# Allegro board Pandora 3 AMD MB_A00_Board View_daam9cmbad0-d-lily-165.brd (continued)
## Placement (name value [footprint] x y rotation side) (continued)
R785  1K/F_4  [R0402]  141.82 133.63 270 bottom
R786  1K/F_4  [R0402]  169.86 105.3 0 top
R787  1K/F_4  [R0402]  170.23 98.85 0 top
R788  2.37K/F_4  [R0402]  133.13 139.96 270 top
R789  2.37K/F_4  [R0402]  151.98 128.17 90 top
R790  2.37K/F_4  [R0402]  176.73 112.31 270 top
R791  2.37K/F_4  [R0402]  162.23 90.08 270 top
R792  5.49K/F_4  [R0402]  131.09 139.96 270 top
R793  5.49K/F_4  [R0402]  152.36 126.65 180 top
R794  5.49K/F_4  [R0402]  177.75 112.31 270 top
R795  5.49K/F_4  [R0402]  163.24 90.08 270 top
R796  2.37K/F_4  [R0402]  129.44 124.72 180 top
R797  2.37K/F_4  [R0402]  149.06 139.86 270 top
R798  2.37K/F_4  [R0402]  164.47 117.36 90 top
R799  2.37K/F_4  [R0402]  177.69 92.73 180 top
R800  5.49K/F_4  [R0402]  129.44 125.74 180 top
R801  5.49K/F_4  [R0402]  151.09 139.86 270 top
R802  5.49K/F_4  [R0402]  164.02 115.97 180 top
R803  5.49K/F_4  [R0402]  178.6 90.45 0 top
R804  2.37K/F_4  [R0402]  123.38 133.13 0 top
R805  2.37K/F_4  [R0402]  156.88 138.18 90 top
R806  2.37K/F_4  [R0402]  173.41 121.14 90 bottom
R807  2.37K/F_4  [R0402]  169.61 83.16 270 bottom
R808  5.49K/F_4  [R0402]  122.87 134.98 90 top
R809  5.49K/F_4  [R0402]  157.27 135.56 180 top
R810  5.49K/F_4  [R0402]  171.12 121.14 90 bottom
R811  5.49K/F_4  [R0402]  170.75 83.16 270 bottom
R812  *s0402_NC  [S0402]  74.56 123.92 270 bottom
R813  *s0402_NC  [S0402]  75.58 123.92 270 bottom
R816  *s0402_NC  [S0402]  71.04 120.93 270 bottom
R817  *s0402_NC  [S0402]  72.05 120.93 270 bottom
R821  6.2K/F_4  [R0402]  248.48 13.44 0 bottom
R831  *s0402_NC  [S0402]  269.58 54.88 0 top
R832  *s0402_NC  [S0402]  269.58 56.02 0 top
R833  *10K/F_4_NC  [R0402]  264.86 50.91 0 top
R834  *10K/F_4_NC  [R0402]  262.95 50.91 0 top
R835  *10K/F_4_NC  [R0402]  266.76 57 90 top
R836  *10K/F_4_NC  [R0402]  265.62 57 270 top
R852  *s0603_NC  [S0603]  217.41 11 180 top
R861  100K_4  [R0402]  220.26 19.54 270 bottom
R862  100K_4  [R0402]  221.86 17.76 270 bottom
R863  4.7K_4  [R0402]  230.95 28.81 90 top
R864  4.7K_4  [R0402]  229.81 28.81 90 top
R865  2.2K_4  [R0402]  226.76 28.81 90 top
R866  2.2K_4  [R0402]  225.06 28.81 90 top
R867  2.2K_4  [R0402]  238.95 23.55 0 top
R868  2.2K_4  [R0402]  238.95 25.2 0 top
R872  100K/F_4  [R0402]  212.91 20.6 180 top
R876  10K/F_4  [R0402]  249.24 36.68 270 bottom
R878  10K/F_4  [R0402]  238.76 24.43 0 bottom
R886  *s0402_NC  [S0402]  193.13 21.34 90 bottom
R899  *0_4_NC  [R0402]  179.69 49.73 0 top
R908  *s0603_NC  [S0603]  246.14 17.66 270 bottom
R909  *s0402_NC  [S0402]  248.48 15.73 0 bottom
R910  *s0402_NC  [S0402]  248.48 14.58 0 bottom
R913  *4.7K_4_NC  [R0402]  104.71 53.19 90 top
R914  *4.7K_4_NC  [R0402]  105.86 53.19 90 top
R915  *s0402_NC  [S0402]  105.25 51.34 90 top
R916  *s0402_NC  [S0402]  106.39 51.34 90 top
R917  4.7K_4  [R0402]  104.71 59.54 90 top
R918  *4.7K_4_NC  [R0402]  106.11 59.54 90 top
R919  *0_4_NC  [R0402]  104.71 57.38 90 top
R920  *s0402_NC  [S0402]  105.82 57.38 90 top
R921  150/F_4  [R0402]  147.13 86.85 90 bottom
R922  *1K/F_4_NC  [R0402]  124.14 103.87 180 bottom
R923  *1K/F_4_NC  [R0402]  122.11 103.87 0 bottom
R924  *1K/F_4_NC  [R0402]  119.97 107.3 180 top
R925  1K/F_4  [R0402]  117.82 106.1 0 top
R926  1K/F_4  [R0402]  140.57 95.94 0 top
R927  *1K/F_4_NC  [R0402]  140.57 94.92 180 top
R928  *1K/F_4_NC  [R0402]  124.14 105.01 180 bottom
R929  1K/F_4  [R0402]  122.11 105.01 0 bottom
R930  1K/F_4  [R0402]  117.79 105.01 0 bottom
R931  *1K/F_4_NC  [R0402]  119.95 105.01 180 bottom
R932  1K/F_4  [R0402]  117.79 103.87 0 bottom
R933  *1K/F_4_NC  [R0402]  119.95 103.87 180 bottom
R934  1K/F_4  [R0402]  119.95 102.72 180 bottom
R935  *1K/F_4_NC  [R0402]  117.79 102.72 0 bottom
R936  *1K/F_4_NC  [R0402]  139.13 93.94 90 top
R937  1K/F_4  [R0402]  138.11 93.94 270 top
R938  1K/F_4  [R0402]  119.95 111.87 0 top
R939  *1K/F_4_NC  [R0402]  119.95 110.72 180 top
R940  *1K/F_4_NC  [R0402]  117.79 114.53 0 top
R941  *1K/F_4_NC  [R0402]  117.79 115.55 180 top
R942  *1K/F_4_NC  [R0402]  117.79 109.45 0 top
R943  *1K/F_4_NC  [R0402]  117.79 110.47 180 top
R944  10/F_4  [R0402]  122.11 110.72 0 bottom
R945  *10/F_4_NC  [R0402]  124.14 110.72 180 bottom
R946  *10/F_4_NC  [R0402]  124.14 109.58 180 bottom
R947  10/F_4  [R0402]  122.11 109.58 0 bottom
R948  *10/F_4_NC  [R0402]  117.79 109.58 0 bottom
R949  10/F_4  [R0402]  119.95 109.58 180 bottom
R950  10/F_4  [R0402]  124.14 108.44 180 bottom
R951  *10/F_4_NC  [R0402]  122.11 108.44 0 bottom
R952  10/F_4  [R0402]  117.79 108.44 0 bottom
R953  *10/F_4_NC  [R0402]  119.95 108.44 180 bottom
R954  10/F_4  [R0402]  117.79 107.48 0 bottom
R955  *10/F_4_NC  [R0402]  119.95 107.29 180 bottom
R956  *10/F_4_NC  [R0402]  124.14 107.29 180 bottom
R957  10/F_4  [R0402]  122.11 107.29 0 bottom
R958  10/F_4  [R0402]  117.79 106.15 0 bottom
R959  *10/F_4_NC  [R0402]  119.95 105.97 180 bottom
R960  *10K/F_NC  [R0402]  122.37 85.7 270 bottom
R962  *s0603_NC  [S0603]  274.97 83.59 180 top
R963  *100K/F_4_NC  [R0402]  221.81 28.81 90 top
R964  *s0402_NC  [S0402]  220.66 28.81 270 top
R965  *10K/F_4_NC  [R0402]  95.95 101.1 180 bottom
R966  10K_4  [R0402]  239 20.43 180 top
R967  10K_4  [R0402]  217.77 25.68 0 top
R970  24.3K/F_4  [R0402]  241.24 13.35 180 top
R971  20K/F_4  [R0402]  239.01 13.35 0 top
R981  *10K/F_4_NC  [R0402]  21.73 18.88 0 bottom
R982  *10K/F_4_NC  [R0402]  20.32 24.49 90 bottom
R983  *10K/F_4_NC  [R0402]  21.31 24.49 270 bottom
R984  *10K/F_4_NC  [R0402]  19.98 18.88 0 bottom
R985  *10K/F_4_NC  [R0402]  21.37 12.35 270 bottom
R986  *10K/F_4_NC  [R0402]  21.73 17.89 0 bottom
R987  *10K/F_4_NC  [R0402]  19.98 17.89 0 bottom
R988  *10K/F_4_NC  [R0402]  20.36 12.35 90 bottom
R994  10K/F_4  [R0402]  88.99 106.05 270 top
R1002  *100K_4_NC  [R0402]  247.03 20.96 0 top
R1003  *15K/F_4_NC  [R0402]  269.43 83.16 90 top
R1004  *0_4_NC  [R0402]  269.3 77.58 180 top
R1005  10K/F_4  [R0402]  228.77 28.81 270 top
R1006  *10K/F_4_NC  [R0402]  97.63 104.3 270 bottom
R1007  10K/F_4  [R0402]  117.01 85.78 0 bottom
R1008  *10K/F_4_NC  [R0402]  95.95 112.09 180 bottom
R1009  *10K/F_4_NC  [R0402]  95.95 111.07 180 bottom
R1010  10K/F_4  [R0402]  78.68 115.93 90 top
R1011  10K/F_4  [R0402]  89.26 103.25 0 top
R1012  10K/F_4  [R0402]  98.16 101.66 90 bottom
R1013  10K/F_4  [R0402]  117.79 116.57 180 top
R1014  *10K/F_4_NC  [R0402]  136.36 83.98 0 top
R1015  *0_4_NC  [R0402]  123.25 83.35 0 bottom
R1016  4.7K_4  [R0402]  123.25 84.32 180 bottom
R1017  *s0402_NC  [S0402]  270.79 50.75 0 top
R1018  *s0402_NC  [S0402]  270.79 51.73 0 top
R1020  *s0402_NC  [S0402]  154.18 51.4 270 bottom
R1021  *10K/F_4_NC  [R0402]  161.28 36.45 0 bottom
R1022  *s0402_NC  [S0402]  160.62 40.41 0 bottom
R1023  *s0402_NC  [S0402]  158.69 36.17 0 bottom
R1024  *s0402_NC  [S0402]  153.97 40.37 0 bottom
R1026  *0_4_NC  [R0402]  155.83 40.36 0 bottom
R1027  10K/F_4  [R0402]  158.77 40.46 0 bottom
R1028  *s0402_NC  [S0402]  157.35 37.57 270 bottom
R1029  *0_4_NC  [R0402]  157.35 39.38 90 bottom
R1030  10K/F_4  [R0402]  153.1 35.79 180 bottom
R1031  *s0402_NC  [S0402]  155.83 41.38 0 bottom
R1032  *0_4_NC  [R0402]  152.1 40.35 0 bottom
R1034  *s0402_NC  [S0402]  148.21 40.26 0 bottom
R1035  *0_4_NC  [R0402]  148.21 39.3 180 bottom
R1036  *s0402_NC  [S0402]  258.1 16.95 270 bottom
R1037  *0_4_NC  [R0402]  182.85 53.82 90 bottom
R1038  *s0402_NC  [S0402]  176.72 42.65 90 top
R1040  10K_4  [R0402]  228.54 30.26 0 top
R1042  *s0402_NC  [S0402]  127.55 52.63 270 bottom
R1043  *s0402_NC  [S0402]  122.11 30.08 270 bottom
R1044  *s0402_NC  [S0402]  212.36 15.31 0 top
R1045  10K_4  [R0402]  242.76 21.32 90 top
R1046  *s0402_NC  [S0402]  243.78 21.32 270 top
R1048  *s0402_NC  [S0402]  223.99 29.11 0 bottom
R1049  *0_4_NC  [R0402]  223.99 28.1 0 bottom
R1050  *s0402_NC  [S0402]  168.86 55.96 180 bottom
R1051  *s0402_NC  [S0402]  171.39 54.08 90 bottom
R1052  *s0402_NC  [S0402]  26.1 13.95 0 top
R1053  *s0402_NC  [S0402]  26.1 12.93 180 top
R1054  *1M_4_NC  [R0402]  17.08 9.5 90 bottom
R1055  *0_4_NC  [R0402]  138.01 28.81 90 bottom
R1056  *22_8_NC  [R0805]  99.3 124.57 90 bottom
R1057  *22_8_NC  [R0805]  77.41 127.35 180 bottom
R1058  *22_8_NC  [R0805]  57.57 126.72 90 bottom
R1059  *22_8_NC  [R0805]  115.93 19.41 0 bottom
R1060  *22_8_NC  [R0805]  18.23 7.22 0 bottom
R1061  *22_8_NC  [R0805]  133.13 25.15 180 bottom
R1062  *22_8_NC  [R0805]  31.18 69.58 90 bottom
R1063  *1M_4_NC  [R0402]  125.82 44.1 90 top
R1064  *0_4_NC  [R0402]  128.46 46.53 180 bottom
R1065  *22_8_NC  [R0805]  123.99 43.28 90 bottom
R1066  *s0402_NC  [S0402]  46.32 115.82 180 bottom
R1067  *100K_4_NC  [R0402]  122.81 89.37 0 bottom
R1068  *s0402_NC  [S0402]  181.42 13.17 0 bottom
R1069  *0_4_NC  [R0402]  12.09 23.03 0 bottom
R1070  8.2K_4  [R0402]  220.16 22.54 90 bottom
R1071  *s0402_NC  [S0402]  217.77 24.24 180 top
R1072  *100K_4_NC  [R0402]  217.87 16.49 0 bottom
R1073  *0_4_NC  [R0402]  153.17 51.4 90 bottom
R1074  100K_4  [R0402]  232.74 31.67 270 top
R1075  *s0402_NC  [S0402]  243.78 23.09 270 top
R1076  *s0402_NC  [S0402]  242.76 23.09 270 top
R1077  *22_8_NC  [R0805]  137.28 79.62 0 bottom
R1078  *1M_4_NC  [R0402]  124.13 80.62 270 bottom
R1079  *0_4_NC  [R0402]  124.4 78.92 0 bottom
R1080  *s0603_NC  [S0603]  263.97 49.72 180 top
R1082  1K/F_4  [R0402]  75.31 120.93 90 bottom
R1083  33_4  [R0402]  140.32 86.76 0 bottom
R1084  33_4  [R0402]  134.48 86.76 0 bottom
R1085  33_4  [R0402]  136.25 86.76 0 bottom
R1086  33_4  [R0402]  138.54 86.76 0 bottom
R1087  *s0402_NC  [S0402]  26.1 7.73 0 top
R1088  *0_4_NC  [R0402]  26.1 6.71 0 top
R1089  *10K_4_NC  [R0402]  236.16 31.6 90 top
R1091  10K/F_4  [R0402]  117.79 113.52 0 top
R1092  *10K/F_4_NC  [R0402]  85.15 120.88 90 bottom
R1093  *10K/F_4_NC  [R0402]  83.76 120.88 90 bottom
R1095  *0_4_NC  [R0402]  142.5 44.81 90 bottom
R1096  *10K/F_4_NC  [R0402]  117.79 111.49 180 top
R1102  *s0402_NC  [S0402]  211.01 20.55 180 top
R1103  *s0402_NC  [S0402]  208.6 20.55 180 top
R1104  *s0402_NC  [S0402]  211.01 21.57 180 top
R1105  *s0402_NC  [S0402]  208.6 21.57 180 top
R1106  *s0402_NC  [S0402]  211.01 22.59 180 top
R1107  10K/F_4  [R0402]  79.69 115.93 90 top
R1108  0_4  [R0402]  200.34 23.73 270 top
R1109  0_4  [R0402]  197.93 26.4 270 top
R1110  0_4  [R0402]  248.48 25.38 0 top
R1111  *0_4_NC  [R0402]  7.15 12.35 270 top
R1112  *s0402_NC  [S0402]  6.19 12.35 270 top
RT1  10K/NTC_4  [R0402]  111.7 50.02 270 bottom
RT2  10K/NTC_4  [R0402]  236.49 14.13 180 bottom
RTCBT1  50271-00201-001  [50271-00201-001-2P-L]  274.72 2.1 180 bottom
RTCD1  BAT54CW-7-F  [SOT323_213-2_1-1_3-2N7002W]  271.34 3.51 90 top
RTCR1  1K/F_4  [R0402]  273.55 4.3 0 top
SJ6  *SJ0201_NC  [S0201]  26.48 29.42 90 top
SJ7  *SJ0201_NC  [S0201]  25.72 29.42 90 top
SJ9  *SJ0603_NC  [S0603]  24.63 30.23 270 top
SJ11  *SJ0201_NC  [S0201]  129.05 18.32 90 bottom
SJ12  *SJ0201_NC  [S0201]  130.06 18.32 90 bottom
SJ13  *SJ0201_NC  [S0201]  165.02 17.41 180 bottom
SJ15  *SJ0201_NC  [S0201]  124.47 37.24 180 bottom
SJ18  *SJ0201_NC  [S0201]  152.07 69.21 90 bottom
SJ19  *SJ0201_NC  [S0201]  151.97 72.97 270 bottom
SJ20  *SJ0201_NC  [S0201]  165.69 75.51 180 bottom
TP15  *PAD_NC  [TP2675]  278.02 84.89 0 top
TP42  *PAD_NC  [TP2650]  166.94 7.63 0 top
TP78  *PAD_NC  [TP2675]  276.11 85.37 0 top
TP79  *PAD_NC  [TP2675]  274.33 86.11 0 top
TP80  *PAD_NC  [TP2650]  266.84 67.06 0 top
TP98  *PAD_NC  [TP2650]  83.63 15.25 180 bottom
TP99  *PAD_NC  [TP2650]  162.4 12.88 180 bottom
TP100  *PAD_NC  [TP2650]  137.4 11.98 0 top
TP101  *PAD_NC  [TP2650]  66 11.21 180 bottom
TP102  *PAD_NC  [TP2650]  88.38 7.9 180 bottom
TP103  *PAD_NC  [TP2650]  139.26 4.91 180 bottom
TP104  *PAD_NC  [TP2650]  72.39 93.27 0 top
TP105  *PAD_NC  [TP2650]  72.34 96.83 0 top
TP106  *PAD_NC  [TP2650]  76.33 95.83 0 top
TP107  *PAD_NC  [TP2650]  78.4 96.91 0 top
TP108  *PAD_NC  [TP2650]  78.04 92.47 0 top
TP109  *PAD_NC  [TP2650]  78.52 94.48 0 top
TP110  *PAD_NC  [TP2650]  51.31 100.76 180 bottom
TP111  *PAD_NC  [TP2650]  50.04 100.76 180 bottom
TP113  *PAD_NC  [TP2050]  79.72 96.25 0 top
TP114  *PAD_NC  [TP2050]  79.89 97.97 0 top
TP115  *PAD_NC  [TP2050]  65.72 97.24 0 top
TP116  *PAD_NC  [TP2050]  64.07 97.41 0 top
TP117  *PAD_NC  [TP2050]  46.17 112.37 180 bottom
TP118  *PAD_NC  [TP2050]  45.91 110.34 180 bottom
TP119  *PAD_NC  [TP2050]  46.93 111.23 180 bottom
TP120  *PAD_NC  [TP2050]  65.26 96.03 0 top
TP121  *PAD_NC  [TP2050]  56.85 105.71 0 top
TP124  *PAD_NC  [TP2050]  94.43 118.34 180 bottom
TP125  *PAD_NC  [TP2050]  95.57 119.11 180 bottom
TP126  *PAD_NC  [TP2050]  78.28 111.77 0 top
TP128  *PAD_NC  [TP2050]  80.92 112.16 0 top
TP133  *PAD_NC  [TP2050]  75.97 110.31 0 top
TP137  *PAD_NC  [TP2050]  80.85 110.88 0 top
TP141  *PAD_NC  [TP2050]  82.28 110.8 0 top
TP144  *PAD_NC  [TP2050]  88.58 121.14 180 bottom
TP145  *PAD_NC  [TP2050]  87.95 122.28 180 bottom
TP146  *PAD_NC  [TP2050]  91.12 121.14 180 bottom
TP153  *PAD_NC  [TP2050]  68.95 93.76 0 top
TP154  *PAD_NC  [TP2050]  68.36 92.05 0 top
TP155  *PAD_NC  [TP2050]  82.4 92.97 0 top
TP178  *PAD_NC  [TP2050]  147.9 83.87 0 top
TP179  *PAD_NC  [TP2050]  144.81 94.49 0 top
TP180  *PAD_NC  [TP2050]  164.66 122.56 0 top
TP245  *PAD_NC  [TP2050]  92.39 121.14 180 bottom
TP246  *PAD_NC  [TP2050]  94.3 119.61 180 bottom
TP249  *PAD_NC  [TP2050]  83.65 104.52 0 top
TP254  *PAD_NC  [TP2050]  88.15 101.98 0 top
TP255  *PAD_NC  [TP2050]  94.5 102.32 180 bottom
TP263  *PAD_NC  [TP2050]  257.37 13.7 180 bottom
TP264  *PAD_NC  [TP2050]  254.7 19.41 180 bottom
TP265  *PAD_NC  [TP2050]  257.2 18.01 180 bottom
TP266  *PAD_NC  [TP2050]  256.86 15.73 180 bottom
TP267  *PAD_NC  [TP2050]  255.78 12.25 180 bottom
TP268  *PAD_NC  [TP2650]  65.6 85.7 180 bottom
TP270  *PAD_NC  [TP2050]  123.58 98.63 180 bottom
TP271  *PAD_NC  [TP2050]  124.19 101.66 180 bottom
TP272  *PAD_NC  [TP2050]  125.11 100.74 180 bottom
TP273  *PAD_NC  [TP2050]  125.74 99.61 180 bottom
TP274  *PAD_NC  [TP2050]  124.47 99.61 180 bottom
TP275  *PAD_NC  [TP2050]  121.48 98.62 180 bottom
TP276  *PAD_NC  [TP2050]  154.36 117.52 180 bottom
TP277  *PAD_NC  [TP2050]  122.5 109.12 0 top
TP278  *PAD_NC  [TP2050]  122.43 107.85 0 top
TP279  *PAD_NC  [TP2050]  122.85 101.76 180 bottom
TP280  *PAD_NC  [TP2050]  131.99 106.63 0 top
TP281  *PAD_NC  [TP2050]  133.24 106.15 0 top
TP286  *PAD_NC  [TP2050]  137.12 94.37 0 top
TP287  *PAD_NC  [TP2050]  136.15 95.3 0 top
TP288  *PAD_NC  [TP2050]  138.14 96.12 0 top
TP289  *PAD_NC  [TP2050]  139.31 95.45 0 top
TP290  *PAD_NC  [TP2675]  234.38 28.81 180 bottom
TP291  *PAD_NC  [TP2675]  231.97 28.55 180 bottom
TP292  *PAD_NC  [TP2675]  235.27 30.84 180 bottom
TP293  *PAD_NC  [TP2675]  232.35 26.65 180 bottom
TP294  *PAD_NC  [TP2675]  140.31 145.04 0 top
TP295  *PAD_NC  [TP2675]  122.41 147.63 0 top
TP296  *PAD_NC  [TP2675]  140.44 147.36 0 top
TP297  *PAD_NC  [TP2675]  121.09 149.37 0 top
TP298  *PAD_NC  [TP2675]  138.65 150.33 0 top
TP299  *PAD_NC  [TP2675]  121.94 144.68 0 top
TP300  *PAD_NC  [TP2675]  238.37 23.41 180 bottom
TP301  *PAD_NC  [TP2675]  249.24 38.33 180 bottom
TP304  *PAD_NC  [TP2050]  125.54 102.65 180 bottom
TP308  *PAD_NC  [TP2050]  86.04 121.14 180 bottom
TP309  *PAD_NC  [TP2050]  87.31 121.14 180 bottom
TP311  *PAD_NC  [TP2050]  132.78 103.36 0 top
TP312  *PAD_NC  [TP2050]  125.54 103.94 180 bottom
TP313  *PAD_NC  [TP2050]  87.06 111.66 0 top
TP314  *PAD_NC  [TP2050]  85.54 110.7 0 top
TP315  *PAD_NC  [TP2050]  85.31 113.82 0 top
TP316  *PAD_NC  [TP2050]  85.81 112.02 0 top
TP317  *PAD_NC  [TP2050]  86.15 106.87 0 top
TP318  *PAD_NC  [TP2050]  83.56 110.46 0 top
TP319  *PAD_NC  [TP2050]  83.02 106.84 0 top
TP320  *PAD_NC  [TP2050]  84.58 106.84 0 top
TP321  *PAD_NC  [TP2050]  129.5 86.82 180 bottom
TP322  *PAD_NC  [TP2050]  82.87 121.01 180 bottom
TP324  *PAD_NC  [TP2050]  104.71 106.91 180 bottom
TP325  *PAD_NC  [TP2050]  218.89 14.58 180 bottom
TP326  *PAD_NC  [TP2050]  46.8 6.33 0 top
TP327  *PAD_NC  [TP2050]  48.71 6.33 0 top
TP328  *PAD_NC  [TP2050]  50.61 6.33 0 top
U2  RTL8111H-CG  [QFN32-4X4-4-33P-0_9H]  271.08 88.4 180 top
U5  PS8407A  [QFN40-5X5-4-50P-0_75H]  271.28 66.65 0 top
U7  TPS2546RTER  [QFN16-3X3-5-17P-TPS2546RTER]  266.88 45.33 0 top
U9  NCT7718W  [TSSOP8-4_9-65]  43.5 109.83 0 bottom
U12  NS692417  [TRF-9_4-1_27-24P]  271.46 100.94 90 bottom
U18  FP4  [BGA968-AMD-FP4]  72.45 103.4 0 bottom
U19  74LVC2G07GW  [SC70-2_1-65-6P-0_95H]  54.29 22.84 0 top
U20  W25Q64FWSSIG  [SOIC8-7_9-1_27]  130.87 147.43 90 top
U21  IC AP2138N-1.5TRG1  [SOT23_213-2_8-1_9-1_45H]  244.29 9.63 90 top
U22  BAFFIN - REV 0.90  [BGA769-AMD-FT3]  140.35 102.15 270 bottom
U24  SN74LV1T08DCKR  [SC70-2_1-65-5P-TLV70033DCKR]  119.88 88.12 180 bottom
U27  Si51214-A1EAGM  [DFN6-1_2X1_4-4]  118.43 82.4 180 bottom
U28  RTS5170-GRT  [QFN24-4X4-5-25P-ALC5629]  253.43 15.98 90 bottom
U29  PTN36001  [QFN12-1_25X2_1-4]  266 53.57 90 top
U33  W25X40CLSSIG  [SOIC8-7_9-1_27]  243.52 38.21 90 bottom
U34  IT8528  [LQFP128-16X16-4-1_6H]  228.57 18.01 270 top
U202  *74LVC1G32GW_NC  [SSOP5-P-A-TOSHIBA-B]  159.76 38.41 0 bottom
U203  74LVC1G32GW  [SSOP5-P-A-TOSHIBA-B]  155.04 38.46 180 bottom
U205  SN74LV1T08DCKR  [SC70-2_1-65-5P-TLV70033DCKR]  151.16 38.49 0 bottom
U206  G524B1T11U  [TSOT23-2_8-95-5P-G916-475TOUF]  169.52 52.29 90 top
U207  G524B1T11U  [TSOT23-2_8-95-5P-G916-475TOUF]  275.21 82.13 90 bottom
U208  *GD25Q21BTIGR_NC  [SOIC8-7_9-1_27]  136.58 83.44 270 bottom
U209  PTN36001  [QFN12-1_25X2_1-4]  21 21.45 90 bottom
U210  PTN36001  [QFN12-1_25X2_1-4]  21.01 15.33 90 bottom
VRAM1  GDDR5  [BGA170-HYNIX-H5GQ1H24MJR]  131.95 133.42 270 bottom
VRAM2  GDDR5  [BGA170-HYNIX-H5GQ1H24MJR]  150.37 133.44 90 bottom
VRAM3  GDDR5  [BGA170-HYNIX-H5GQ1H24MJR]  171.12 112.14 180 bottom
VRAM4  GDDR5  [BGA170-HYNIX-H5GQ1H24MJR]  171.11 92.15 0 bottom
Y1  25MHz  [XTL-3_2X2_5-2_2X1_7-4P]  277.56 88.01 90 top
Y3  32.768KHZ  [XTL-3_2X1_5-2_5-0_8H]  101.7 115.37 180 top
Y4  48MHZ +-15PPM  [XTL-3_2X2_5-2_2X1_8-4P]  68.21 124.4 180 bottom
Y6  27MHZ +-10PPM  [XTL-3_2X2_5-2_2X1_7]  112.97 82.67 90 bottom

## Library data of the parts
C8-C23 C341 C359 C481 C496 C632 C635 C760 C762 C763 C770 C782-C784 C798-C800 C802-C809 C811-C814 C818 C823-C828 C844-C853 C864-C871 C873 C879 C881 C884 C886 C947-C962 C1041-C1060 C1122 C1123 C1125-C1127 C1131 EC11-EC18 = C_20
C199 C215 C254 C287 C302 C310 C323 C336 = V-PORT
C225 C391 C464 C482 C483 C489 C502 C573 C574 C623 C665 C682 C684 C690 C691 C747 C748 C1210 C9366 C9373-C9376 CS1-CS4 CS6 CS8 = C_43
C228 C334 C343 C345 C347 C352 C356 C360 C371 C497 C513 C529 C531 C624-C628 C642 C643 C645 C666-C669 C675 C676 C700 C701 C771 C774 C789 C790 C817 C819-C822 C842 C843 C878 C880 C882 C883 C885 C910-C916 C940-C946 C991-C994 C996 C998-C1000 C1009-C1011 C1025 C1026 C1039 C1040 C1070 C1089 C1175-C1178 C1181-C1183 C1190 C1211 C1236 C9385-C9388 EC54-EC57 EC59-EC62 EC65-EC81 = C
C339 C370 = CAP NP_2
C357 C754-C756 C768 C769 C888 C899 C907 C908 C918 C928 C929 C937 C938 C970 C971 C973 C974 C977 C978 C980-C990 C1002-C1008 C1012-C1024 C1027-C1038 C1061-C1069 C1071-C1088 C1090-C1098 C9382 EC24 EC25 EC28 EC32 EC33 EC63 EC64 EC90 EC91 = C_22
C413 C415 C593 C659 EC26 = Passive_C
C414 C418-C425 C459 C463 C479 C486 C509 C512 C530 C661-C664 C689 C740-C742 C745 C746 C1103-C1106 C1225 C1227 C9370 C9377 C9378 = C_24
C458 C503 C504 C674 EC30 = C_28
C478 PC9302 PC9303 = C_16
C485 = C_60
C487 C490 C688 EC139 EC142 EC144 EC146 EC147 EC151 EC155 EC157 EC159-EC161 PC144 PC9095-PC9097 PC9103 PC9112 PC9113 PC9115 PC9122 PC9123 PC9128 PC9129 PC9133 PC9137 PC9144 PC9147 PC9148 PC9150 PC9156 PC9158 PC9159 PC9165 PC9170 PC9178 PC9190-PC9193 PC9216 PC9217 PC9238 PC9239 PC9242 PC9243 PC9256 PC9258 PC9260 PC9265 PC9266 PC9269 PC9270 PC9276 PC9278 PC9285-PC9289 PC9296 PC9338 PC9344 PC9345 PC9348 PC9349 PC9359-PC9361 PC9371-PC9375 = C_0
C517 C712 C716 = C_3
C526 C533 = C_27
C634 C735 C744 = C_25
C638 C648 C692 C703 C725 C729 C730 C733 = C_23
C660 C1231 C1232 EC34 EC89 EC140 EC141 EC143 EC145 EC148 EC152-EC154 EC156 EC158 PC191 PC234 PC235 PC240 PC243 PC244 PC9222 PC9230 PC9355 = C_49
C681 C9379-C9381 C9383 C9396-C9405 EC20 EC29 EC35 EC36 EC42-EC45 EC87 EC88 EC162-EC166 PC79 PC81-PC90 PC188 PC221 PC224-PC228 PC230-PC232 PC236-PC239 PC241 PC242 PC245-PC253 PC9354 PC9376 = C_47
C694 C723 C1107-C1121 = C_21
C714 C728 C734 C964 C965 C1188 C1238 C1239 C9367 = C_26
C724 = C_37
C739 EC31 PC138 = C_29
C743 C9368 C9369 = _0_0.1UF
C749-C753 C757-C759 C761 C766 C767 C772 C773 C775-C777 C779 C785-C788 C792 C793 C801 C810 C815 C816 C829-C841 C854 C860 C862 C863 C872 C874 C887 C889 C896 C906 C909 C917 C919 C926 C936 C939 C995 C997 C1099 C1100 C1200 C1202 C1206 C1209 C9384 C9389-C9395 = 0_1.1U
C764 C9362-C9365 C9371 C9372 PC147 PC9305-PC9318 PC9320 PC9322-PC9329 PC9332 PC9334-PC9337 PC9362 PC9363 PC9365 PC9367 = C_17
C875 C877 = _0_0.1UF_Y5V
C876 = C_18
C890-C895 C897 C898 C900-C905 C920-C925 C927 C930-C935 EC37 = C_30
C968 C969 PC9125 PC9162 PC9252 PC9271 = C_10
C979 = CAP NP_4
C1001 = CAPACITOR POL_4
C1132-C1135 C1138-C1144 C1191 C1192 C1212-C1223 C1230 = CAP NON-POL_BGM_1
C1237 PC233 PC9094 PC9098-PC9102 PC9104-PC9107 PC9111 PC9114 PC9116 PC9124 PC9126 PC9127 PC9131 PC9132 PC9134-PC9136 PC9141 PC9142 PC9145 PC9146 PC9149 PC9151 PC9157 PC9161 PC9163 PC9164 PC9166 PC9171 PC9174-PC9177 PC9186 PC9200-PC9202 PC9208 PC9211 PC9212 PC9221 PC9234 PC9240 PC9241 PC9244-PC9247 PC9251 PC9253-PC9255 PC9259 PC9261 PC9264 PC9268 PC9272-PC9275 PC9279 PC9281-PC9284 PC9295 PC9297 PC9298 PC9319 PC9321 PC9333 PC9340 PC9346 PC9350 PC9368 PC9369 = C_32
CN1 = Header_4P_BGM
CN2 = HEADER 24_0
CN3 = CON-TP_5
CN4 = CON-TP_2
CN5 = GS12401-1011_6
CN6 = HEADER RJ-45 FOX LED_0
CN7 = CON_HDMI_A_2
CN8 = USB3_0
CN9 = GS12401-1011_2
CN10 = NGFF_CONN_RDC_1
CN11 = CON9_0
CN12 = Serial ATA_0
CN13 = HDR10X2_DEBUG_0
CN16 = DDR4-4mm_0
CN17 = DDR4-8mm_0
CON1 = NGFF CONN_SATA_1
D1 D2 D6 D21-D23 D28-D30 D42 D43 D46 D50 D52 = RB751VAC_4
D3-D5 D15 D16 = CHN202_0
D17-D19 = DIODE
EC38 = C_31
EL3 = BW_2
EL14 = INDUCTOR_5
ESD1 = CDA6C05GTH_0
EU1 = TI TPS2556DRBR_0
FAN1 FAN2 = 53398-0410_0
FL1 FL2 PL18-PL22 PL27 PL28 = INDUCTOR_1
FS1 = POLY SW_0
H1 H2 H7 H19 H20 = HOLE
H3-H6 H8-H11 = HOLE: User Part Number: ***; Tolerance: ***
H12 H13 H16-H18 = HOLE: Tolerance: ***; User Part Number: ***
HDMIF1 PR222 R394 = R_0
J1 J2 = 53398_0
J3 = 53398_1
JBAT1 = BATTCON3_8
JCARD1 = CS1S-318-H-N_0
JP51 = OPEN
L14 L15 = INDUCTOR_0
PAD1 PAD2 = 3x2_0.1
PC142 PC9364 PC9366 = CAP NP_5
PC151 = CAP NP_3
PC222 PC223 = CAPACITOR POL_0
PC229 = C_48
PC9092 PC9093 PC9110 PC9120 PC9121 PC9130 PC9140 PC9155 PC9160 PC9169 PC9173 PC9250 PC9262 PC9263 PC9267 PC9277 PC9280 PC9357 PC9358 = CAPACITOR POL_5
PC9108 PC9109 PC9117 PC9119 PC9138 PC9143 PC9152-PC9154 PC9167 PC9168 PC9172 PC9248 PC9249 = C_9
PC9194 PC9219 PC9290 PC9343 = C_11
PC9195-PC9199 PC9225-PC9229 PC9291-PC9294 PC9341 PC9342 PC9347 PC9351 PC9356 PC9370 = C_1
PC9203 PC9205 PC9206 PC9330 PC9331 PC9353 = CAP NP_1
PC9204 PC9207 = CAPACITOR NON-POL_0
PC9209 = _1.1UF
PC9210 PC9214 PC9233 PC9237 = C_19
PC9213 PC9235 PC9236 = CAP NP_0
PC9299-PC9301 PC9304 = C_15
PD1 PD5 PD6 = DA204U_0
PD2 PD7 = DIODE_0
PD3 PD4 = DIODE_1
PL15 = INDUCTOR_3
PL16 PL17 PL24-PL26 PL29 PL31 = INDUCTOR_2
PQ28 Q4 = NPN_0
PQ29 PQ30 PQ63-PQ68 Q8 Q11 Q26 Q37 Q42 = 2N7002
PQ31 PQ36 = 2N7002-EBC_1
PQ32 PQ33 PQ35 PQ37-PQ41 PQ57 = SI4410DY
PQ42 PQ52 PQ58 PQ73 = SI4410DY_0
PQ43 Q23 = 2N7002DW_1
PQ44 = PNP_0
PQ45-PQ49 PQ59-PQ62 = MOSFET_NCH_DUAL_0
PQ53 PQ54 PQ72 = SI3442DV_0
PQ70 PQ71 Q13 Q16 Q25 Q31 Q40 = 2N7002DW
PR60-PR62 PR175 PR178 PR185 PR186 PR193 PR194 PR196 PR202-PR204 PR207-PR210 PR214 PR225 PR228 PR229 PR234-PR237 PR242-PR245 PR249-PR251 PR253 PR255-PR257 PR259 PR260 PR274 PR282 PR283 PR287-PR289 PR291-PR293 PR295 PR298 PR299 PR313 PR328 PR331-PR337 PR339 PR343 PR366 PR369 PR370 PR382 PR393-PR396 PR399-PR401 PR403 PR426 PR427 PR430-PR433 PR435-PR437 PR443 PR484 PR485 PR515 R393 R399 R417 R459 = R_28
PR103 PR121 R398 = R_38
PR107 R523 R526-R528 R536 R539 R541 R543 R545 R546 R549-R552 R569 R572 R574 R578 R580 R582 R583 R586 R628 R635 R707 R711 R763 R764 R960 R965 R981-R988 R994 R1005-R1007 R1010-R1014 R1052 R1053 R1071 R1092 R1093 R1102-R1107 RTCR1 = R_35
PR111 PR120 PR270 PR360 PR455-PR457 PR460 PR461 PR479 PR480 PR498 PR501 PR502 PR504 PR506 PR507 PR509 PR513 PR514 = R_14
PR113 R508-R510 R512 R514-R518 R520 R571 R627 R629 R630 R632 R634 R636 R638 R640 R643 R644 R646 R648 R657 R658 R666 R667 R768-R779 R788-R811 R1020-R1024 R1026-R1032 R1034 R1035 R1073 = R_31
PR115 R55 R75 R178 R179 R435 R436 R443 R445 R447 R448 R530 R863-R868 R966 R967 R1089 = R_34
PR187-PR192 PR199 R43 R45 R53 R54 R83 R84 R150 R151 R170-R173 R560 R641 R642 = R_41
PR195 PR201 R239 R352 = R_43
PR200 PR205 PR211 PR215 PR230 PR247 PR264-PR269 PR273 PR297 PR300 PR309 PR311 PR312 PR314 PR316 PR321 PR342 PR346 PR353 PR373 PR391 PR406 PR410 PR411 PR413 PR414 PR416 PR442 PR445 PR450 PR463 PR465 PR494-PR496 PR508 PR510-PR512 = SJ
PR206 = R_27
PR217 PR218 = R_66
PR220 PR232 = SI3441DV_0
PR221 PR223 PR224 PR493 R645 R647 R649 R650 R780-R787 = R_40
PR226 PR227 PR246 PR252 PR254 PR271 PR290 PR294 PR301 PR305 PR308 PR330 PR338 PR347 PR359 PR362-PR364 PR386 PR390 PR392 PR397 PR408 PR429 PR438 PR446 PR447 PR452-PR454 PR469 PR471 PR474 PR475 PR481 PR483 R231-R233 R236 R242 R1069 R1108-R1112 = R_4
PR258 PR296 PR340 PR361 PR402 PR439 PR451 PR472 = R_10
PR261 PR279 PR302 PR317 PR341 PR404 PR417 PR440 R625 R852 = R_42
PR263 PR276 PR278 PR280 PR281 PR284 PR285 PR303 PR304 PR307 PR310 PR318 PR319 PR322 PR324 PR326 PR344 PR345 PR368 PR405 PR407 PR409 PR418 PR419 PR421 PR423-PR425 PR441 PR444 PR458 PR462 PR478 PR492 PR499 PR500 PR503 PR505 R1055 R1064 R1079 = R_6
PR275 PR277 PR323 PR420 PR422 = 10K-0603-1%: tolerance: 1%
PR325 PR327 = R_5
PR374 PR375 PR387 PR388 = R_19
PR398 PR412 PR434 R1056-R1062 R1065 R1077 = R_45
PR449 PR477 = R_8
PR467 PR468 = R_16
PU2 = RT8207_0
PU9 = G5388K11U_2
PU15 = MAX8731EEI_0
PU16 PU17 PU24 = ISL62771HRZ-T_15
PU18 PU25 = TPS51117RGYR-GP_1
PU19 = TPS51117RGYR-GP_0
PU20 = SC338_2
PU21 PU23 = G966_0
PU27-PU29 = G923_0
PU30 = LM393
Q6 Q12 Q17 Q21 Q30 Q45 Q49-Q64 = 2N7002W_0
Q7 = IRLML5103
Q9 = DMN5L06DWK/50V_2.3A-BAM5L060002
Q20 = UN5114
Q32 Q33 = DMN5L06DWK/50V_0.3A-BAM5L060002
Q36 = 2N7002_3
Q41 = 2N7002D
Q44 = DMN5L06DWK/50V_1.3A-BAM5L060002
R58 R73 R570 R872 R963 R1003 = R_17
R92 R94-R97 R138 R159 R161-R163 R202 R226 R228 R234 R246 R248 R320 R325 R329 R333 R336 R340 R341 R344-R349 R358 R359 R376-R379 R404 R433 R452 R453 R460 R494 R495 R511 R679 R831 R832 R886 R899 R909 R910 R913-R920 R964 R1004 R1017 R1018 R1036-R1038 R1042-R1044 R1046 R1048-R1051 R1068 R1075 R1076 R1087 R1088 R1091 R1095 R1096 = R_32
R93 R471-R476 R513 R519 R589 R590 R592-R598 R602-R605 R621 R651 R747-R750 = R_30
R110 R112 R117 R128 R132 R133 R262 R669 R672 = R
R118 R122 R135 R861 R862 R970 R971 R1002 R1067 R1072 R1074 = R_46
R201 R238 R324 R330 R337 R342 R1040 R1045 = Passive_R
R235 R241 = R_39
R263 = R_7
R264 R416 R461-R464 R467 R468 R484 R486 R521 R522 R531 R553 R562 R576 R579 R581 R587 R588 R591 R599-R601 R606-R612 R681 R683 R688 R690 R691 R693 R697-R699 R705 R709 R717 R719 R720 R762 R922-R959 R1015 R1054 R1063 R1078 R1082-R1086 = R_49
R303 = R_24
R321 R615-R619 R622-R624 R674 R675 R731 R732 R765-R767 R1016 = R_36
R350 = R_44
R397 = R_69
R415 = R_1
R446 = R_37
R469 R470 R477-R483 R485 R487-R493 R496-R502 R506 R507 R524 R525 R532-R535 R537 R538 R540 R542 R544 R547 R548 R554-R559 R561 R563 R568 R573 R1008 R1009 = RES
R503 R505 R584 R585 R613 R614 R812 R813 R816 R817 R876 R878 R1066 = R_33
R652 = R_23
R664 R665 R670 R673 = R_22
R668 R671 = R_20
R821 R833-R836 R908 R921 R962 R1080 = RES_BGM
R1070 = R_47
RT1 = P_6.8KB_0603_5%_ERTJ1VR682J~D
RT2 = P_0.8KB_0603_5%_ERTJ1VR682J~D
RTCBT1 = HEADER 3_1
RTCD1 = DIODE SCHOTTKY_1
SJ6 SJ7 SJ9 = SJ_2
SJ11-SJ13 = SJ_0
SJ15 SJ18-SJ20 = SJ_1
TP15 TP78 TP79 TP124-TP126 TP128 TP133 TP137 TP245 TP246 TP249 TP254 TP255 TP263-TP267 TP290-TP301 TP308 TP309 TP313-TP320 TP322 TP324-TP328 = PAD_6
TP42 TP98-TP103 = PAD_7
TP80 TP178-TP180 TP321 = PAD_0
TP104-TP111 TP146 TP268 = PAD_1
TP113-TP120 TP153-TP155 TP286-TP289 TP304 TP311 TP312 = PAD_4
TP121 TP141 TP144 TP145 TP270-TP281 = PAD_5
U2 = RL5877_0
U5 = PS8401A_1
U7 = TPS2540_0
U9 = LM86_0
U12 = NS680016_0
U18 = FP4_1
U19 = AL07WV07000
U20 U208 = SST25LF080A_0
U21 = IMISM530_2
U22 = BAFFIN
U24 U205 = 7SH08_2
U27 = SI51214
U28 = RTS5170-GRT_BGM
U29 U209 U210 = PTN36001_BGM
U33 = IC,FLASH,SPI,16M,2.5V,SOIC-W,8,
U34 = IT8512_0
U202 U203 = NL17SZ32DFT2G_BGM
U206 U207 = G524B1T11U_BGM
VRAM1-VRAM4 = 170BALL_GDDR5_1
Y1 = CRYSTAL2_0
Y3 = CRYSTAL1_1
Y4 = CRYSTAL2_3
Y6 = CRYSTAL2_5

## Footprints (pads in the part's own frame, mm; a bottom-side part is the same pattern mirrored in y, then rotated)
50271-00201-001-2P-L
  rect 0.787x1.6 smd: 1(-0.625,2.9) 2(0.625,2.9)
  rect 2.108x2.997 smd: 3(-3.175,0) 4(3.175,0)
50278-00401-001-4P-L
  rect 0.787x1.905 smd: 1(-1.875,4.925) 2(-0.625,4.925) 3(0.625,4.925) 4(1.875,4.925)
  rect 1.295x3.353 smd: 5(-4.725,0) 6(4.725,0)
50281-00401-001-4P-L
  rect 0.787x2.007 smd: 1(-1.875,4.05) 2(-0.625,4.05) 3(0.625,4.05) 4(1.875,4.05)
  rect 2.007x2.489 smd: 5(-4.075,0) 6(4.075,0)
50288-01171-V01-11P-L
  rect 0.711x3.505 smd: 1(-7.5,2) 2(-6,2) 3(-4.5,2) 4(-3,2) 5(-1.5,2) 6(0,2) 7(1.5,2) 8(3,2) 9(4.5,2) 10(6,2) 11(7.5,2)
  rect 1.499x2.311 smd: 12(-9.55,0) 13(9.55,0)
50293-0087N-002-8P-LDV_AB
  rect 0.838x3.556 smd: A1(-5.25,-2.5) A2(-3.75,-2.5) A3(-2.25,-2.5) A4(-0.75,-2.5) A5(0.75,-2.5) A6(2.25,-2.5) A7(3.75,-2.5) A8(5.25,-2.5)
  rect 0.838x2.642 smd: B1(-5.25,1.4) B2(-3.75,1.4) B3(-2.25,1.4) B4(-0.75,1.4) B5(0.75,1.4) B6(2.25,1.4) B7(3.75,1.4) B8(5.25,1.4)
50503-0080N-001-8P-L
  rect 0.508x1.295 smd: 1(-3.5,1.4) 2(-2.5,1.4) 3(-1.5,1.4) 4(-0.5,1.4) 5(0.5,1.4) 6(1.5,1.4) 7(2.5,1.4) 8(3.5,1.4)
  rect 1.803x1.397 smd: 9(-5.65,-1.4) 10(5.65,-1.4)
50505-00401-V01-4P-L
  rect 0.61x1.295 smd: 1(-1.5,3.25) 2(-0.5,3.25) 3(0.5,3.25) 4(1.5,3.25)
  rect 0.991x2.007 smd: 5(-4.1,0) 6(4.1,0)
50506-00601-V01-6P-L
  rect 0.305x0.889 smd: 1(-1.25,3.05) 2(-0.75,3.05) 3(-0.25,3.05) 4(0.25,3.05) 5(0.75,3.05) 6(1.25,3.05)
  rect 0.991x2.007 smd: 7(-3.35,0) 8(3.35,0)
51575-00401-V01-4P-L
  rect 0.406x0.838 smd: 1(-1.5,3.175) 2(-0.5,3.175) 3(0.5,3.175) 4(1.5,3.175)
  rect 0.787x2.007 smd: 5(-3.7,0) 6(3.7,0)
51643-03001-V01-30P-L
  rect 0.305x1.295 smd: 1(-11.6,5.65) 2(-10.8,5.65) 3(-10,5.65) 4(-9.2,5.65) 5(-8.4,5.65) 6(-7.6,5.65) 7(-6.8,5.65) 8(-6,5.65) 9(-5.2,5.65) 10(-4.4,5.65) 11(-3.6,5.65) 12(-2.8,5.65) 13(-2,5.65) 14(-1.2,5.65) 15(-0.4,5.65) 16(0.4,5.65) 17(1.2,5.65) 18(2,5.65) 19(2.8,5.65) 20(3.6,5.65) 21(4.4,5.65) 22(5.2,5.65) 23(6,5.65) 24(6.8,5.65) 25(7.6,5.65) 26(8.4,5.65) 27(9.2,5.65) 28(10,5.65) 29(10.8,5.65) 30(11.6,5.65)
  rect 1.803x2.21 smd: 31(-13.95,0) 32(13.95,0)
88266-080L-8P-L
  rect 0.787x2.007 smd: 1(-4.375,4.05) 2(-3.125,4.05) 3(-1.875,4.05) 4(-0.625,4.05) 5(0.625,4.05) 6(1.875,4.05) 7(3.125,4.05) 8(4.375,4.05)
  rect 2.007x2.489 smd: 9(-6.575,0) 10(6.575,0)
ASP-137098-05-20P-LDV
  rect 0.737x2.794 smd: 1(-5.715,-2.035) 2(-5.715,2.035) 3(-4.445,-2.035) 4(-4.445,2.035) 5(-3.175,-2.035) 6(-3.175,2.035) 7(-1.905,-2.035) 8(-1.905,2.035) 9(-0.635,-2.035) 10(-0.635,2.035) 11(0.635,-2.035) 12(0.635,2.035) 13(1.905,-2.035) 14(1.905,2.035) 15(3.175,-2.035) 16(3.175,2.035) 17(4.445,-2.035) 18(4.445,2.035) 19(5.715,-2.035) 20(5.715,2.035)
BGA170-HYNIX-H5GQ1H24MJR
  round 0.356 smd: A1(-6.4,-5.2) A2(-6.4,-4.4) A3(-6.4,-3.6) A4(-6.4,-2.8) A5(-6.4,-2) A10(-6.4,2) A11(-6.4,2.8) A12(-6.4,3.6) A13(-6.4,4.4) A14(-6.4,5.2) B1(-5.6,-5.2) B2(-5.6,-4.4) B3(-5.6,-3.6) B4(-5.6,-2.8) B5(-5.6,-2) B10(-5.6,2) B11(-5.6,2.8) B12(-5.6,3.6) B13(-5.6,4.4) B14(-5.6,5.2) C1(-4.8,-5.2) C2(-4.8,-4.4) C3(-4.8,-3.6) C4(-4.8,-2.8) C5(-4.8,-2) C10(-4.8,2) C11(-4.8,2.8) C12(-4.8,3.6) C13(-4.8,4.4) C14(-4.8,5.2) D1(-4,-5.2) D2(-4,-4.4) D3(-4,-3.6) D4(-4,-2.8) D5(-4,-2) D10(-4,2) D11(-4,2.8) D12(-4,3.6) D13(-4,4.4) D14(-4,5.2) E1(-3.2,-5.2) E2(-3.2,-4.4) E3(-3.2,-3.6) E4(-3.2,-2.8) E5(-3.2,-2) E10(-3.2,2) E11(-3.2,2.8) E12(-3.2,3.6) E13(-3.2,4.4) E14(-3.2,5.2) F1(-2.4,-5.2) F2(-2.4,-4.4) F3(-2.4,-3.6) F4(-2.4,-2.8) F5(-2.4,-2) F10(-2.4,2) F11(-2.4,2.8) F12(-2.4,3.6) F13(-2.4,4.4) F14(-2.4,5.2) G1(-1.6,-5.2) G2(-1.6,-4.4) G3(-1.6,-3.6) G4(-1.6,-2.8) G5(-1.6,-2) G10(-1.6,2) G11(-1.6,2.8) G12(-1.6,3.6) G13(-1.6,4.4) G14(-1.6,5.2) H1(-0.8,-5.2) H2(-0.8,-4.4) H3(-0.8,-3.6) H4(-0.8,-2.8) H5(-0.8,-2) H10(-0.8,2) H11(-0.8,2.8) H12(-0.8,3.6) H13(-0.8,4.4) H14(-0.8,5.2) J1(0,-5.2) J2(0,-4.4) J3(0,-3.6) J4(0,-2.8) J5(0,-2) J10(0,2) J11(0,2.8) J12(0,3.6) J13(0,4.4) J14(0,5.2) K1(0.8,-5.2) K2(0.8,-4.4) K3(0.8,-3.6) K4(0.8,-2.8) K5(0.8,-2) K10(0.8,2) K11(0.8,2.8) K12(0.8,3.6) K13(0.8,4.4) K14(0.8,5.2) L1(1.6,-5.2) L2(1.6,-4.4) L3(1.6,-3.6) L4(1.6,-2.8) L5(1.6,-2) L10(1.6,2) L11(1.6,2.8) L12(1.6,3.6) L13(1.6,4.4) L14(1.6,5.2) M1(2.4,-5.2) M2(2.4,-4.4) M3(2.4,-3.6) M4(2.4,-2.8) M5(2.4,-2) M10(2.4,2) M11(2.4,2.8) M12(2.4,3.6) M13(2.4,4.4) M14(2.4,5.2) N1(3.2,-5.2) N2(3.2,-4.4) N3(3.2,-3.6) N4(3.2,-2.8) N5(3.2,-2) N10(3.2,2) N11(3.2,2.8) N12(3.2,3.6) N13(3.2,4.4) N14(3.2,5.2) P1(4,-5.2) P2(4,-4.4) P3(4,-3.6) P4(4,-2.8) P5(4,-2) P10(4,2) P11(4,2.8) P12(4,3.6) P13(4,4.4) P14(4,5.2) R1(4.8,-5.2) R2(4.8,-4.4) R3(4.8,-3.6) R4(4.8,-2.8) R5(4.8,-2) R10(4.8,2) R11(4.8,2.8) R12(4.8,3.6) R13(4.8,4.4) R14(4.8,5.2) T1(5.6,-5.2) T2(5.6,-4.4) T3(5.6,-3.6) T4(5.6,-2.8) T5(5.6,-2) T10(5.6,2) T11(5.6,2.8) T12(5.6,3.6) T13(5.6,4.4) T14(5.6,5.2) U1(6.4,-5.2) U2(6.4,-4.4) U3(6.4,-3.6) U4(6.4,-2.8) U5(6.4,-2) U10(6.4,2) U11(6.4,2.8) U12(6.4,3.6) U13(6.4,4.4) U14(6.4,5.2)
BGA769-AMD-FT3
  round 0.4 smd: A2(-11.3,-10.7) A3(-11.3,-9.95) A39(-11.3,9.95) A40(-11.3,10.7) AA4(0,-9.2) AA5(0,-8.4) AA7(0,-7.6) AA8(0,-6.8) AA10(0,-6) AA11(0,-5) AA13(0,-4) AA15(0,-3) AA17(0,-2) AA19(0,-1) AA21(0,0) AA23(0,1) AA25(0,2) AA27(0,3) AA29(0,4) AA31(0,5) AA32(0,6) AA34(0,6.8) AA35(0,7.6) AA37(0,8.4) AA38(0,9.2) AC4(1.1,-9.2) AC5(1.1,-8.4) AC7(1.1,-7.6) AC8(1.1,-6.8) AC10(1.1,-6) AC11(1,-5) AC13(1,-4) AC15(1,-3) AC17(1,-2) AC19(1,-1) AC21(1,0) AC23(1,1) AC25(1,2) AC27(1,3) AC29(1,4) AC31(1,5) AC32(1.1,6) AC34(1.1,6.8) AC35(1.1,7.6) AC37(1.1,8.4) AC38(1.1,9.2) AE4(2.2,-9.2) AE5(2.2,-8.4) AE7(2.2,-7.6) AE8(2.2,-6.8) AE10(2.2,-6) AE11(2,-5) AE13(2,-4) AE15(2,-3) AE17(2,-2) AE19(2,-1) AE21(2,0) AE23(2,1) AE25(2,2) AE27(2,3) AE29(2,4) AE31(2,5) AE32(2.2,6) AE34(2.2,6.8) AE35(2.2,7.6) AE37(2.2,8.4) AE38(2.2,9.2) AG4(3.3,-9.2) AG5(3.3,-8.4) AG7(3.3,-7.6) AG8(3.3,-6.8) AG10(3.3,-6) AG11(3,-5) AG13(3,-4) AG15(3,-3) AG17(3,-2) AG19(3,-1) AG21(3,0) AG23(3,1) AG25(3,2) AG27(3,3) AG29(3,4) AG31(3,5) AG32(3.3,6) AG34(3.3,6.8) AG35(3.3,7.6) AG37(3.3,8.4) AG38(3.3,9.2) AJ4(4.4,-9.2) AJ5(4.4,-8.4) AJ7(4.4,-7.6) AJ8(4.4,-6.8) AJ10(4.4,-6) AJ11(4,-5) AJ13(4,-4) AJ15(4,-3) AJ17(4,-2) AJ19(4,-1) AJ21(4,0) AJ23(4,1) AJ25(4,2) AJ27(4,3) AJ29(4,4) AJ31(4,5) AJ32(4.4,6) AJ34(4.4,6.8) AJ35(4.4,7.6) AJ37(4.4,8.4) AJ38(4.4,9.2) AL4(5.5,-9.2) AL5(5.5,-8.4) AL7(5.5,-7.6) AL8(5.5,-6.8) AL10(5.5,-6) AL11(5,-5) AL13(5,-4) AL15(5,-3) AL17(5,-2) AL19(5,-1) AL21(5,0) AL23(5,1) AL25(5,2) AL27(5,3) AL29(5,4) AL31(5,5) AL32(5.5,6) AL34(5.5,6.8) AL35(5.5,7.6) AL37(5.5,8.4) AL38(5.5,9.2) AM11(6,-5.5) AM13(6,-4.4) AM15(6,-3.3) AM17(6,-2.2) AM19(6,-1.1) AM21(6,0) AM23(6,1.1) AM25(6,2.2) AM27(6,3.3) AM29(6,4.4) AM31(6,5.5) AN4(6.6,-9.2) AN5(6.6,-8.4) AN7(6.6,-7.6) AN8(6.6,-6.8) AN34(6.6,6.8) AN35(6.6,7.6) AN37(6.6,8.4) AN38(6.6,9.2) AP11(6.8,-5.5) AP13(6.8,-4.4) AP15(6.8,-3.3) AP17(6.8,-2.2) AP19(6.8,-1.1) AP21(6.8,0) AP23(6.8,1.1) AP25(6.8,2.2) AP27(6.8,3.3) AP29(6.8,4.4) AP31(6.8,5.5) AR4(7.7,-9.2) AR5(7.7,-8.4) AR7(7.7,-7.6) AR11(7.6,-5.5) AR13(7.6,-4.4) AR15(7.6,-3.3) AR17(7.6,-2.2) AR19(7.6,-1.1) AR21(7.6,0) AR23(7.6,1.1) AR25(7.6,2.2) AR27(7.6,3.3) AR29(7.6,4.4) AR31(7.6,5.5) AR35(7.7,7.6) AR37(7.7,8.4) AR38(7.7,9.2) AU4(8.8,-9.2) AU7(8.4,-7.7) AU9(8.4,-6.6) AU11(8.4,-5.5) AU13(8.4,-4.4) AU15(8.4,-3.3) AU17(8.4,-2.2) AU19(8.4,-1.1) AU21(8.4,0) AU23(8.4,1.1) AU25(8.4,2.2) AU27(8.4,3.3) AU29(8.4,4.4) AU31(8.4,5.5) AU33(8.4,6.6) AU35(8.4,7.7) AU38(8.8,9.2) AV7(9.2,-7.7) AV9(9.2,-6.6) AV11(9.2,-5.5) AV13(9.2,-4.4) AV15(9.2,-3.3) AV17(9.2,-2.2) AV19(9.2,-1.1) AV21(9.2,0) AV23(9.2,1.1) AV25(9.2,2.2) AV27(9.2,3.3) AV29(9.2,4.4) AV31(9.2,5.5) AV33(9.2,6.6) AV35(9.2,7.7) AW1(9.95,-11.3) AW41(9.95,11.3) AY1(10.7,-11.3) AY2(10.6,-10.6) AY40(10.6,10.6) AY41(10.7,11.3) B1(-10.7,-11.3) B2(-10.6,-10.6) B40(-10.6,10.6) B41(-10.7,11.3) BA2(11.3,-10.7) BA3(11.3,-9.95) BA39(11.3,9.95) BA40(11.3,10.7) C1(-9.95,-11.3) C41(-9.95,11.3) D7(-9.2,-7.7) D9(-9.2,-6.6) D11(-9.2,-5.5) D13(-9.2,-4.4) D15(-9.2,-3.3) D17(-9.2,-2.2) D19(-9.2,-1.1) D21(-9.2,0) D23(-9.2,1.1) D25(-9.2,2.2) D27(-9.2,3.3) D29(-9.2,4.4) D31(-9.2,5.5) D33(-9.2,6.6) D35(-9.2,7.7) E4(-8.8,-9.2) E7(-8.4,-7.7) E9(-8.4,-6.6) E11(-8.4,-5.5) E13(-8.4,-4.4) E15(-8.4,-3.3) E17(-8.4,-2.2) E19(-8.4,-1.1) E21(-8.4,0) E23(-8.4,1.1) E25(-8.4,2.2) E27(-8.4,3.3) E29(-8.4,4.4) E31(-8.4,5.5) E33(-8.4,6.6) E35(-8.4,7.7) E38(-8.8,9.2) G4(-7.7,-9.2) G5(-7.7,-8.4) G7(-7.7,-7.6) G11(-7.6,-5.5) G13(-7.6,-4.4) G15(-7.6,-3.3) G17(-7.6,-2.2) G19(-7.6,-1.1) G21(-7.6,0) G23(-7.6,1.1) G25(-7.6,2.2) G27(-7.6,3.3) G29(-7.6,4.4) G31(-7.6,5.5) G35(-7.7,7.6) G37(-7.7,8.4) G38(-7.7,9.2) H11(-6.8,-5.5) H13(-6.8,-4.4) H15(-6.8,-3.3) H17(-6.8,-2.2) H19(-6.8,-1.1) H21(-6.8,0) H23(-6.8,1.1) H25(-6.8,2.2) H27(-6.8,3.3) H29(-6.8,4.4) H31(-6.8,5.5) J4(-6.6,-9.2) J5(-6.6,-8.4) J7(-6.6,-7.6) J8(-6.6,-6.8) J34(-6.6,6.8) J35(-6.6,7.6) J37(-6.6,8.4) J38(-6.6,9.2) K11(-6,-5.5) K13(-6,-4.4) K15(-6,-3.3) K17(-6,-2.2) K19(-6,-1.1) K21(-6,0) K23(-6,1.1) K25(-6,2.2) K27(-6,3.3) K29(-6,4.4) K31(-6,5.5) L4(-5.5,-9.2) L5(-5.5,-8.4) L7(-5.5,-7.6) L8(-5.5,-6.8) L10(-5.5,-6) L11(-5,-5) L13(-5,-4) L15(-5,-3) L17(-5,-2) L19(-5,-1) L21(-5,0) L23(-5,1) L25(-5,2) L27(-5,3) L29(-5,4) L31(-5,5) L32(-5.5,6) L34(-5.5,6.8) L35(-5.5,7.6) L37(-5.5,8.4) L38(-5.5,9.2) N4(-4.4,-9.2) N5(-4.4,-8.4) N7(-4.4,-7.6) N8(-4.4,-6.8) N10(-4.4,-6) N11(-4,-5) N13(-4,-4) N15(-4,-3) N17(-4,-2) N19(-4,-1) N21(-4,0) N23(-4,1) N25(-4,2) N27(-4,3) N29(-4,4) N31(-4,5) N32(-4.4,6) N34(-4.4,6.8) N35(-4.4,7.6) N37(-4.4,8.4) N38(-4.4,9.2) R4(-3.3,-9.2) R5(-3.3,-8.4) R7(-3.3,-7.6) R8(-3.3,-6.8) R10(-3.3,-6) R11(-3,-5) R13(-3,-4) R15(-3,-3) R17(-3,-2) R19(-3,-1) R21(-3,0) R23(-3,1) R25(-3,2) R27(-3,3) R29(-3,4) R31(-3,5) R32(-3.3,6) R34(-3.3,6.8) R35(-3.3,7.6) R37(-3.3,8.4) R38(-3.3,9.2) U4(-2.2,-9.2) U5(-2.2,-8.4) U7(-2.2,-7.6) U8(-2.2,-6.8) U10(-2.2,-6) U11(-2,-5) U13(-2,-4) U15(-2,-3) U17(-2,-2) U19(-2,-1) U21(-2,0) U23(-2,1) U25(-2,2) U27(-2,3) U29(-2,4) U31(-2,5) U32(-2.2,6) U34(-2.2,6.8) U35(-2.2,7.6) U37(-2.2,8.4) U38(-2.2,9.2) W4(-1.1,-9.2) W5(-1.1,-8.4) W7(-1.1,-7.6) W8(-1.1,-6.8) W10(-1.1,-6) W11(-1,-5) W13(-1,-4) W15(-1,-3) W17(-1,-2) W19(-1,-1) W21(-1,0) W23(-1,1) W25(-1,2) W27(-1,3) W29(-1,4) W31(-1,5) W32(-1.1,6) W34(-1.1,6.8) W35(-1.1,7.6) W37(-1.1,8.4) W38(-1.1,9.2)
  round 0.3 smd: A4(-10.95,-9.35) A5(-11.3,-8.8) A6(-10.95,-8.25) A7(-11.3,-7.7) A8(-10.95,-7.15) A9(-11.3,-6.6) A10(-10.95,-6.05) A11(-11.3,-5.5) A12(-10.95,-4.95) A13(-11.3,-4.4) A14(-10.95,-3.85) A15(-11.3,-3.3) A16(-10.95,-2.75) A17(-11.3,-2.2) A18(-10.95,-1.65) A19(-11.3,-1.1) A20(-10.95,-0.55) A21(-11.3,0) A22(-10.95,0.55) A23(-11.3,1.1) A24(-10.95,1.65) A25(-11.3,2.2) A26(-10.95,2.75) A27(-11.3,3.3) A28(-10.95,3.85) A29(-11.3,4.4) A30(-10.95,4.95) A31(-11.3,5.5) A32(-10.95,6.05) A33(-11.3,6.6) A34(-10.95,7.15) A35(-11.3,7.7) A36(-10.95,8.25) A37(-11.3,8.8) A38(-10.95,9.35) AA1(0,-11.3) AA2(0,-10.6) AA3(0,-9.9) AA39(0,9.9) AA40(0,10.6) AA41(0,11.3) AB1(0.55,-10.95) AB2(0.55,-10.25) AB40(0.55,10.25) AB41(0.55,10.95) AC1(1.1,-11.3) AC2(1.1,-10.6) AC3(1.1,-9.9) AC39(1.1,9.9) AC40(1.1,10.6) AC41(1.1,11.3) AD1(1.65,-10.95) AD2(1.65,-10.25) AD40(1.65,10.25) AD41(1.65,10.95) AE1(2.2,-11.3) AE2(2.2,-10.6) AE3(2.2,-9.9) AE39(2.2,9.9) AE40(2.2,10.6) AE41(2.2,11.3) AF1(2.75,-10.95) AF2(2.75,-10.25) AF40(2.75,10.25) AF41(2.75,10.95) AG1(3.3,-11.3) AG2(3.3,-10.6) AG3(3.3,-9.9) AG39(3.3,9.9) AG40(3.3,10.6) AG41(3.3,11.3) AH1(3.85,-10.95) AH2(3.85,-10.25) AH40(3.85,10.25) AH41(3.85,10.95) AJ1(4.4,-11.3) AJ2(4.4,-10.6) AJ3(4.4,-9.9) AJ39(4.4,9.9) AJ40(4.4,10.6) AJ41(4.4,11.3) AK1(4.95,-10.95) AK2(4.95,-10.25) AK40(4.95,10.25) AK41(4.95,10.95) AL1(5.5,-11.3) AL2(5.5,-10.6) AL3(5.5,-9.9) AL39(5.5,9.9) AL40(5.5,10.6) AL41(5.5,11.3) AM1(6.05,-10.95) AM2(6.05,-10.25) AM40(6.05,10.25) AM41(6.05,10.95) AN1(6.6,-11.3) AN2(6.6,-10.6) AN3(6.6,-9.9) AN39(6.6,9.9) AN40(6.6,10.6) AN41(6.6,11.3) AP1(7.15,-10.95) AP2(7.15,-10.25) AP40(7.15,10.25) AP41(7.15,10.95) AR1(7.7,-11.3) AR2(7.7,-10.6) AR3(7.7,-9.9) AR39(7.7,9.9) AR40(7.7,10.6) AR41(7.7,11.3) AT1(8.25,-10.95) AT2(8.25,-10.25) AT40(8.25,10.25) AT41(8.25,10.95) AU1(8.8,-11.3) AU2(8.8,-10.6) AU3(8.8,-9.9) AU39(8.8,9.9) AU40(8.8,10.6) AU41(8.8,11.3) AV1(9.35,-10.95) AV2(9.35,-10.25) AV40(9.35,10.25) AV41(9.35,10.95) AW2(9.9,-10.6) AW3(9.9,-9.9) AW5(9.9,-8.8) AW7(9.9,-7.7) AW9(9.9,-6.6) AW11(9.9,-5.5) AW13(9.9,-4.4) AW15(9.9,-3.3) AW17(9.9,-2.2) AW19(9.9,-1.1) AW21(9.9,0) AW23(9.9,1.1) AW25(9.9,2.2) AW27(9.9,3.3) AW29(9.9,4.4) AW31(9.9,5.5) AW33(9.9,6.6) AW35(9.9,7.7) AW37(9.9,8.8) AW39(9.9,9.9) AW40(9.9,10.6) AY3(10.6,-9.9) AY4(10.25,-9.35) AY5(10.6,-8.8) AY6(10.25,-8.25) AY7(10.6,-7.7) AY8(10.25,-7.15) AY9(10.6,-6.6) AY10(10.25,-6.05) AY11(10.6,-5.5) AY12(10.25,-4.95) AY13(10.6,-4.4) AY14(10.25,-3.85) AY15(10.6,-3.3) AY16(10.25,-2.75) AY17(10.6,-2.2) AY18(10.25,-1.65) AY19(10.6,-1.1) AY20(10.25,-0.55) AY21(10.6,0) AY22(10.25,0.55) AY23(10.6,1.1) AY24(10.25,1.65) AY25(10.6,2.2) AY26(10.25,2.75) AY27(10.6,3.3) AY28(10.25,3.85) AY29(10.6,4.4) AY30(10.25,4.95) AY31(10.6,5.5) AY32(10.25,6.05) AY33(10.6,6.6) AY34(10.25,7.15) AY35(10.6,7.7) AY36(10.25,8.25) AY37(10.6,8.8) AY38(10.25,9.35) AY39(10.6,9.9) B3(-10.6,-9.9) B4(-10.25,-9.35) B5(-10.6,-8.8) B6(-10.25,-8.25) B7(-10.6,-7.7) B8(-10.25,-7.15) B9(-10.6,-6.6) B10(-10.25,-6.05) B11(-10.6,-5.5) B12(-10.25,-4.95) B13(-10.6,-4.4) B14(-10.25,-3.85) B15(-10.6,-3.3) B16(-10.25,-2.75) B17(-10.6,-2.2) B18(-10.25,-1.65) B19(-10.6,-1.1) B20(-10.25,-0.55) B21(-10.6,0) B22(-10.25,0.55) B23(-10.6,1.1) B24(-10.25,1.65) B25(-10.6,2.2) B26(-10.25,2.75) B27(-10.6,3.3) B28(-10.25,3.85) B29(-10.6,4.4) B30(-10.25,4.95) B31(-10.6,5.5) B32(-10.25,6.05) B33(-10.6,6.6) B34(-10.25,7.15) B35(-10.6,7.7) B36(-10.25,8.25) B37(-10.6,8.8) B38(-10.25,9.35) B39(-10.6,9.9) BA4(10.95,-9.35) BA5(11.3,-8.8) BA6(10.95,-8.25) BA7(11.3,-7.7) BA8(10.95,-7.15) BA9(11.3,-6.6) BA10(10.95,-6.05) BA11(11.3,-5.5) BA12(10.95,-4.95) BA13(11.3,-4.4) BA14(10.95,-3.85) BA15(11.3,-3.3) BA16(10.95,-2.75) BA17(11.3,-2.2) BA18(10.95,-1.65) BA19(11.3,-1.1) BA20(10.95,-0.55) BA21(11.3,0) BA22(10.95,0.55) BA23(11.3,1.1) BA24(10.95,1.65) BA25(11.3,2.2) BA26(10.95,2.75) BA27(11.3,3.3) BA28(10.95,3.85) BA29(11.3,4.4) BA30(10.95,4.95) BA31(11.3,5.5) BA32(10.95,6.05) BA33(11.3,6.6) BA34(10.95,7.15) BA35(11.3,7.7) BA36(10.95,8.25) BA37(11.3,8.8) BA38(10.95,9.35) C2(-9.9,-10.6) C3(-9.9,-9.9) C5(-9.9,-8.8) C7(-9.9,-7.7) C9(-9.9,-6.6) C11(-9.9,-5.5) C13(-9.9,-4.4) C15(-9.9,-3.3) C17(-9.9,-2.2) C19(-9.9,-1.1) C21(-9.9,0) C23(-9.9,1.1) C25(-9.9,2.2) C27(-9.9,3.3) C29(-9.9,4.4) C31(-9.9,5.5) C33(-9.9,6.6) C35(-9.9,7.7) C37(-9.9,8.8) C39(-9.9,9.9) C40(-9.9,10.6) D1(-9.35,-10.95) D2(-9.35,-10.25) D40(-9.35,10.25) D41(-9.35,10.95) E1(-8.8,-11.3) E2(-8.8,-10.6) E3(-8.8,-9.9) E39(-8.8,9.9) E40(-8.8,10.6) E41(-8.8,11.3) F1(-8.25,-10.95) F2(-8.25,-10.25) F40(-8.25,10.25) F41(-8.25,10.95) G1(-7.7,-11.3) G2(-7.7,-10.6) G3(-7.7,-9.9) G39(-7.7,9.9) G40(-7.7,10.6) G41(-7.7,11.3) H1(-7.15,-10.95) H2(-7.15,-10.25) H40(-7.15,10.25) H41(-7.15,10.95) J1(-6.6,-11.3) J2(-6.6,-10.6) J3(-6.6,-9.9) J39(-6.6,9.9) J40(-6.6,10.6) J41(-6.6,11.3) K1(-6.05,-10.95) K2(-6.05,-10.25) K40(-6.05,10.25) K41(-6.05,10.95) L1(-5.5,-11.3) L2(-5.5,-10.6) L3(-5.5,-9.9) L39(-5.5,9.9) L40(-5.5,10.6) L41(-5.5,11.3) M1(-4.95,-10.95) M2(-4.95,-10.25) M40(-4.95,10.25) M41(-4.95,10.95) N1(-4.4,-11.3) N2(-4.4,-10.6) N3(-4.4,-9.9) N39(-4.4,9.9) N40(-4.4,10.6) N41(-4.4,11.3) P1(-3.85,-10.95) P2(-3.85,-10.25) P40(-3.85,10.25) P41(-3.85,10.95) R1(-3.3,-11.3) R2(-3.3,-10.6) R3(-3.3,-9.9) R39(-3.3,9.9) R40(-3.3,10.6) R41(-3.3,11.3) T1(-2.75,-10.95) T2(-2.75,-10.25) T40(-2.75,10.25) T41(-2.75,10.95) U1(-2.2,-11.3) U2(-2.2,-10.6) U3(-2.2,-9.9) U39(-2.2,9.9) U40(-2.2,10.6) U41(-2.2,11.3) V1(-1.65,-10.95) V2(-1.65,-10.25) V40(-1.65,10.25) V41(-1.65,10.95) W1(-1.1,-11.3) W2(-1.1,-10.6) W3(-1.1,-9.9) W39(-1.1,9.9) W40(-1.1,10.6) W41(-1.1,11.3) Y1(-0.55,-10.95) Y2(-0.55,-10.25) Y40(-0.55,10.25) Y41(-0.55,10.95)
BGA968-AMD-FP4
  round 0.4 smd: A2(-16.9,-12) A3(-16.9,-11.1) A31(-16.9,11.1) A32(-16.9,12) AB5(0,-9.7) AB6(0,-8.9) AB7(0,-8.1) AB8(0,-7.3) AB9(0,-6.5) AB10(0,-5.4) AB12(0,-4.2) AB13(0,-3) AB15(0,-1.8) AB16(0,-0.6) AB18(0,0.6) AB19(0,1.8) AB21(0,3) AB22(0,4.2) AB24(0,5.4) AB25(0,6.5) AB26(0,7.3) AB27(0,8.1) AB28(0,8.9) AB29(0,9.7) AD5(1.2,-9.7) AD6(1.2,-8.9) AD7(1.2,-8.1) AD8(1.2,-7.3) AD9(1.2,-6.5) AD10(1.2,-5.4) AD12(1.2,-4.2) AD13(1.2,-3) AD15(1.2,-1.8) AD16(1.2,-0.6) AD18(1.2,0.6) AD19(1.2,1.8) AD21(1.2,3) AD22(1.2,4.2) AD24(1.2,5.4) AD25(1.2,6.5) AD26(1.2,7.3) AD27(1.2,8.1) AD28(1.2,8.9) AD29(1.2,9.7) AE5(2.4,-9.7) AE6(2.4,-8.9) AE7(2.4,-8.1) AE8(2.4,-7.3) AE9(2.4,-6.5) AE10(2.4,-5.4) AE12(2.4,-4.2) AE13(2.4,-3) AE15(2.4,-1.8) AE16(2.4,-0.6) AE18(2.4,0.6) AE19(2.4,1.8) AE21(2.4,3) AE22(2.4,4.2) AE24(2.4,5.4) AE25(2.4,6.5) AE26(2.4,7.3) AE27(2.4,8.1) AE28(2.4,8.9) AE29(2.4,9.7) AG5(3.6,-9.7) AG6(3.6,-8.9) AG7(3.6,-8.1) AG8(3.6,-7.3) AG9(3.6,-6.5) AG10(3.6,-5.4) AG12(3.6,-4.2) AG13(3.6,-3) AG15(3.6,-1.8) AG16(3.6,-0.6) AG18(3.6,0.6) AG19(3.6,1.8) AG21(3.6,3) AG22(3.6,4.2) AG24(3.6,5.4) AG25(3.6,6.5) AG26(3.6,7.3) AG27(3.6,8.1) AG28(3.6,8.9) AG29(3.6,9.7) AH5(4.8,-9.7) AH6(4.8,-8.9) AH7(4.8,-8.1) AH8(4.8,-7.3) AH9(4.8,-6.5) AH10(4.8,-5.4) AH12(4.8,-4.2) AH13(4.8,-3) AH15(4.8,-1.8) AH16(4.8,-0.6) AH18(4.8,0.6) AH19(4.8,1.8) AH21(4.8,3) AH22(4.8,4.2) AH24(4.8,5.4) AH25(4.8,6.5) AH26(4.8,7.3) AH27(4.8,8.1) AH28(4.8,8.9) AH29(4.8,9.7) AK5(6,-9.7) AK6(6,-8.9) AK7(6,-8.1) AK8(6,-7.3) AK9(6,-6.5) AK10(6,-5.4) AK12(6,-4.2) AK13(6,-3) AK15(6,-1.8) AK16(6,-0.6) AK18(6,0.6) AK19(6,1.8) AK21(6,3) AK22(6,4.2) AK24(6,5.4) AK25(6,6.5) AK26(6,7.3) AK27(6,8.1) AK28(6,8.9) AK29(6,9.7) AL5(7.2,-9.7) AL6(7.2,-8.9) AL7(7.2,-8.1) AL8(7.2,-7.3) AL9(7.2,-6.5) AL10(7.2,-5.4) AL12(7.2,-4.2) AL13(7.2,-3) AL15(7.2,-1.8) AL16(7.2,-0.6) AL18(7.2,0.6) AL19(7.2,1.8) AL21(7.2,3) AL22(7.2,4.2) AL24(7.2,5.4) AL25(7.2,6.5) AL26(7.2,7.3) AL27(7.2,8.1) AL28(7.2,8.9) AL29(7.2,9.7) AN5(8.4,-9.7) AN6(8.4,-8.9) AN7(8.4,-8.1) AN8(8.4,-7.3) AN9(8.4,-6.5) AN10(8.4,-5.4) AN12(8.4,-4.2) AN13(8.4,-3) AN15(8.4,-1.8) AN16(8.4,-0.6) AN18(8.4,0.6) AN19(8.4,1.8) AN21(8.4,3) AN22(8.4,4.2) AN24(8.4,5.4) AN25(8.4,6.5) AN26(8.4,7.3) AN27(8.4,8.1) AN28(8.4,8.9) AN29(8.4,9.7) AP5(9.6,-9.7) AP6(9.6,-8.9) AP7(9.6,-8.1) AP8(9.6,-7.3) AP9(9.6,-6.5) AP10(9.6,-5.4) AP12(9.6,-4.2) AP13(9.6,-3) AP15(9.6,-1.8) AP16(9.6,-0.6) AP18(9.6,0.6) AP19(9.6,1.8) AP21(9.6,3) AP22(9.6,4.2) AP24(9.6,5.4) AP25(9.6,6.5) AP26(9.6,7.3) AP27(9.6,8.1) AP28(9.6,8.9) AP29(9.6,9.7) AR5(10.8,-9.7) AR6(10.8,-8.9) AR7(10.8,-8.1) AR8(10.8,-7.3) AR9(10.5,-6) AR11(10.5,-4.8) AR12(10.5,-3.6) AR14(10.5,-2.4) AR15(10.5,-1.2) AR17(10.5,0) AR19(10.5,1.2) AR20(10.5,2.4) AR22(10.5,3.6) AR23(10.5,4.8) AR25(10.5,6) AR26(10.8,7.3) AR27(10.8,8.1) AR28(10.8,8.9) AR29(10.8,9.7) AT9(11.3,-6) AT11(11.3,-4.8) AT12(11.3,-3.6) AT14(11.3,-2.4) AT15(11.3,-1.2) AT17(11.3,0) AT19(11.3,1.2) AT20(11.3,2.4) AT22(11.3,3.6) AT23(11.3,4.8) AT25(11.3,6) AU5(12,-9.7) AU6(12,-8.9) AU7(12,-8.1) AU8(12.1,-7.2) AU9(12.1,-6) AU11(12.1,-4.8) AU12(12.1,-3.6) AU14(12.1,-2.4) AU15(12.1,-1.2) AU17(12.1,0) AU19(12.1,1.2) AU20(12.1,2.4) AU22(12.1,3.6) AU23(12.1,4.8) AU25(12.1,6) AU26(12.1,7.2) AU27(12,8.1) AU28(12,8.9) AU29(12,9.7) AV5(13.2,-9.7) AV7(12.9,-8.4) AV8(12.9,-7.2) AV9(12.9,-6) AV11(12.9,-4.8) AV12(12.9,-3.6) AV14(12.9,-2.4) AV15(12.9,-1.2) AV17(12.9,0) AV19(12.9,1.2) AV20(12.9,2.4) AV22(12.9,3.6) AV23(12.9,4.8) AV25(12.9,6) AV26(12.9,7.2) AV27(12.9,8.4) AV29(13.2,9.7) AW7(13.7,-8.4) AW8(13.7,-7.2) AW9(13.7,-6) AW11(13.7,-4.8) AW12(13.7,-3.6) AW14(13.7,-2.4) AW15(13.7,-1.2) AW17(13.7,0) AW19(13.7,1.2) AW20(13.7,2.4) AW22(13.7,3.6) AW23(13.7,4.8) AW25(13.7,6) AW26(13.7,7.2) AW27(13.7,8.4) B1(-16,-12.9) B2(-16,-12) B32(-16,12) B33(-16,12.9) BA1(15.1,-12.9) BA33(15.1,12.9) BB1(16,-12.9) BB2(16,-12) BB32(16,12) BB33(16,12.9) BC2(16.9,-12) BC3(16.9,-11.1) BC31(16.9,11.1) BC32(16.9,12) C1(-15.1,-12.9) C33(-15.1,12.9) E7(-13.7,-8.4) E8(-13.7,-7.2) E9(-13.7,-6) E11(-13.7,-4.8) E12(-13.7,-3.6) E14(-13.7,-2.4) E15(-13.7,-1.2) E17(-13.7,0) E19(-13.7,1.2) E20(-13.7,2.4) E22(-13.7,3.6) E23(-13.7,4.8) E25(-13.7,6) E26(-13.7,7.2) E27(-13.7,8.4) F5(-13.2,-9.7) F7(-12.9,-8.4) F8(-12.9,-7.2) F9(-12.9,-6) F11(-12.9,-4.8) F12(-12.9,-3.6) F14(-12.9,-2.4) F15(-12.9,-1.2) F17(-12.9,0) F19(-12.9,1.2) F20(-12.9,2.4) F22(-12.9,3.6) F23(-12.9,4.8) F25(-12.9,6) F26(-12.9,7.2) F27(-12.9,8.4) F29(-13.2,9.7) G5(-12,-9.7) G6(-12,-8.9) G7(-12,-8.1) G8(-12.1,-7.2) G9(-12.1,-6) G11(-12.1,-4.8) G12(-12.1,-3.6) G14(-12.1,-2.4) G15(-12.1,-1.2) G17(-12.1,0) G19(-12.1,1.2) G20(-12.1,2.4) G22(-12.1,3.6) G23(-12.1,4.8) G25(-12.1,6) G26(-12.1,7.2) G27(-12,8.1) G28(-12,8.9) G29(-12,9.7) H9(-11.3,-6) H11(-11.3,-4.8) H12(-11.3,-3.6) H14(-11.3,-2.4) H15(-11.3,-1.2) H17(-11.3,0) H19(-11.3,1.2) H20(-11.3,2.4) H22(-11.3,3.6) H23(-11.3,4.8) H25(-11.3,6) J5(-10.8,-9.7) J6(-10.8,-8.9) J7(-10.8,-8.1) J8(-10.8,-7.3) J9(-10.5,-6) J11(-10.5,-4.8) J12(-10.5,-3.6) J14(-10.5,-2.4) J15(-10.5,-1.2) J17(-10.5,0) J19(-10.5,1.2) J20(-10.5,2.4) J22(-10.5,3.6) J23(-10.5,4.8) J25(-10.5,6) J26(-10.8,7.3) J27(-10.8,8.1) J28(-10.8,8.9) J29(-10.8,9.7) K5(-9.6,-9.7) K6(-9.6,-8.9) K7(-9.6,-8.1) K8(-9.6,-7.3) K9(-9.6,-6.5) K10(-9.6,-5.4) K12(-9.6,-4.2) K13(-9.6,-3) K15(-9.6,-1.8) K16(-9.6,-0.6) K18(-9.6,0.6) K19(-9.6,1.8) K21(-9.6,3) K22(-9.6,4.2) K24(-9.6,5.4) K25(-9.6,6.5) K26(-9.6,7.3) K27(-9.6,8.1) K28(-9.6,8.9) K29(-9.6,9.7) L5(-8.4,-9.7) L6(-8.4,-8.9) L7(-8.4,-8.1) L8(-8.4,-7.3) L9(-8.4,-6.5) L10(-8.4,-5.4) L12(-8.4,-4.2) L13(-8.4,-3) L15(-8.4,-1.8) L16(-8.4,-0.6) L18(-8.4,0.6) L19(-8.4,1.8) L21(-8.4,3) L22(-8.4,4.2) L24(-8.4,5.4) L25(-8.4,6.5) L26(-8.4,7.3) L27(-8.4,8.1) L28(-8.4,8.9) L29(-8.4,9.7) N5(-7.2,-9.7) N6(-7.2,-8.9) N7(-7.2,-8.1) N8(-7.2,-7.3) N9(-7.2,-6.5) N10(-7.2,-5.4) N12(-7.2,-4.2) N13(-7.2,-3) N15(-7.2,-1.8) N16(-7.2,-0.6) N18(-7.2,0.6) N19(-7.2,1.8) N21(-7.2,3) N22(-7.2,4.2) N24(-7.2,5.4) N25(-7.2,6.5) N26(-7.2,7.3) N27(-7.2,8.1) N28(-7.2,8.9) N29(-7.2,9.7) P5(-6,-9.7) P6(-6,-8.9) P7(-6,-8.1) P8(-6,-7.3) P9(-6,-6.5) P10(-6,-5.4) P12(-6,-4.2) P13(-6,-3) P15(-6,-1.8) P16(-6,-0.6) P18(-6,0.6) P19(-6,1.8) P21(-6,3) P22(-6,4.2) P24(-6,5.4) P25(-6,6.5) P26(-6,7.3) P27(-6,8.1) P28(-6,8.9) P29(-6,9.7) T5(-4.8,-9.7) T6(-4.8,-8.9) T7(-4.8,-8.1) T8(-4.8,-7.3) T9(-4.8,-6.5) T10(-4.8,-5.4) T12(-4.8,-4.2) T13(-4.8,-3) T15(-4.8,-1.8) T16(-4.8,-0.6) T18(-4.8,0.6) T19(-4.8,1.8) T21(-4.8,3) T22(-4.8,4.2) T24(-4.8,5.4) T25(-4.8,6.5) T26(-4.8,7.3) T27(-4.8,8.1) T28(-4.8,8.9) T29(-4.8,9.7) U5(-3.6,-9.7) U6(-3.6,-8.9) U7(-3.6,-8.1) U8(-3.6,-7.3) U9(-3.6,-6.5) U10(-3.6,-5.4) U12(-3.6,-4.2) U13(-3.6,-3) U15(-3.6,-1.8) U16(-3.6,-0.6) U18(-3.6,0.6) U19(-3.6,1.8) U21(-3.6,3) U22(-3.6,4.2) U24(-3.6,5.4) U25(-3.6,6.5) U26(-3.6,7.3) U27(-3.6,8.1) U28(-3.6,8.9) U29(-3.6,9.7) W5(-2.4,-9.7) W6(-2.4,-8.9) W7(-2.4,-8.1) W8(-2.4,-7.3) W9(-2.4,-6.5) W10(-2.4,-5.4) W12(-2.4,-4.2) W13(-2.4,-3) W15(-2.4,-1.8) W16(-2.4,-0.6) W18(-2.4,0.6) W19(-2.4,1.8) W21(-2.4,3) W22(-2.4,4.2) W24(-2.4,5.4) W25(-2.4,6.5) W26(-2.4,7.3) W27(-2.4,8.1) W28(-2.4,8.9) W29(-2.4,9.7) Y5(-1.2,-9.7) Y6(-1.2,-8.9) Y7(-1.2,-8.1) Y8(-1.2,-7.3) Y9(-1.2,-6.5) Y10(-1.2,-5.4) Y12(-1.2,-4.2) Y13(-1.2,-3) Y15(-1.2,-1.8) Y16(-1.2,-0.6) Y18(-1.2,0.6) Y19(-1.2,1.8) Y21(-1.2,3) Y22(-1.2,4.2) Y24(-1.2,5.4) Y25(-1.2,6.5) Y26(-1.2,7.3) Y27(-1.2,8.1) Y28(-1.2,8.9) Y29(-1.2,9.7)
  round 0.3 smd: A4(-16.5,-10.4) A5(-16.9,-9.6) A6(-16.5,-8.8) A7(-16.9,-8) A8(-16.5,-7.2) A9(-16.9,-6.4) A10(-16.5,-5.6) A11(-16.9,-4.8) A12(-16.5,-4) A13(-16.9,-3.2) A14(-16.5,-2.4) A15(-16.9,-1.6) A16(-16.5,-0.8) A17(-16.9,0) A18(-16.5,0.8) A19(-16.9,1.6) A20(-16.5,2.4) A21(-16.9,3.2) A22(-16.5,4) A23(-16.9,4.8) A24(-16.5,5.6) A25(-16.9,6.4) A26(-16.5,7.2) A27(-16.9,8) A28(-16.5,8.8) A29(-16.9,9.6) A30(-16.5,10.4) AA1(-0.8,-12.9) AA2(-0.8,-12.1) AA3(-0.8,-11.3) AA4(-0.8,-10.5) AA30(-0.8,10.5) AA31(-0.8,11.3) AA32(-0.8,12.1) AA33(-0.8,12.9) AB1(0,-12.5) AB2(0,-11.7) AB4(0,-10.5) AB30(0,10.5) AB32(0,11.7) AB33(0,12.5) AC1(0.8,-12.9) AC2(0.8,-12.1) AC3(0.8,-11.3) AC4(0.8,-10.5) AC30(0.8,10.5) AC31(0.8,11.3) AC32(0.8,12.1) AC33(0.8,12.9) AD1(1.6,-12.5) AD2(1.6,-11.7) AD4(1.6,-10.5) AD30(1.6,10.5) AD32(1.6,11.7) AD33(1.6,12.5) AE1(2.4,-12.9) AE2(2.4,-12.1) AE3(2.4,-11.3) AE4(2.4,-10.5) AE30(2.4,10.5) AE31(2.4,11.3) AE32(2.4,12.1) AE33(2.4,12.9) AF1(3.2,-12.5) AF2(3.2,-11.7) AF4(3.2,-10.5) AF30(3.2,10.5) AF32(3.2,11.7) AF33(3.2,12.5) AG1(4,-12.9) AG2(4,-12.1) AG3(4,-11.3) AG4(4,-10.5) AG30(4,10.5) AG31(4,11.3) AG32(4,12.1) AG33(4,12.9) AH1(4.8,-12.5) AH2(4.8,-11.7) AH4(4.8,-10.5) AH30(4.8,10.5) AH32(4.8,11.7) AH33(4.8,12.5) AJ1(5.6,-12.9) AJ2(5.6,-12.1) AJ3(5.6,-11.3) AJ4(5.6,-10.5) AJ30(5.6,10.5) AJ31(5.6,11.3) AJ32(5.6,12.1) AJ33(5.6,12.9) AK1(6.4,-12.5) AK2(6.4,-11.7) AK4(6.4,-10.5) AK30(6.4,10.5) AK32(6.4,11.7) AK33(6.4,12.5) AL1(7.2,-12.9) AL2(7.2,-12.1) AL3(7.2,-11.3) AL4(7.2,-10.5) AL30(7.2,10.5) AL31(7.2,11.3) AL32(7.2,12.1) AL33(7.2,12.9) AM1(8,-12.5) AM2(8,-11.7) AM4(8,-10.5) AM30(8,10.5) AM32(8,11.7) AM33(8,12.5) AN1(8.8,-12.9) AN2(8.8,-12.1) AN3(8.8,-11.3) AN4(8.8,-10.5) AN30(8.8,10.5) AN31(8.8,11.3) AN32(8.8,12.1) AN33(8.8,12.9) AP1(9.6,-12.5) AP2(9.6,-11.7) AP4(9.6,-10.5) AP30(9.6,10.5) AP32(9.6,11.7) AP33(9.6,12.5) AR1(10.4,-12.9) AR2(10.4,-12.1) AR3(10.4,-11.3) AR4(10.4,-10.5) AR30(10.4,10.5) AR31(10.4,11.3) AR32(10.4,12.1) AR33(10.4,12.9) AT1(11.2,-12.5) AT2(11.2,-11.7) AT4(11.2,-10.5) AT30(11.2,10.5) AT32(11.2,11.7) AT33(11.2,12.5) AU1(12,-12.9) AU2(12,-12.1) AU3(12,-11.3) AU4(12,-10.5) AU30(12,10.5) AU31(12,11.3) AU32(12,12.1) AU33(12,12.9) AV1(12.8,-12.5) AV2(12.8,-11.7) AV4(12.8,-10.5) AV30(12.8,10.5) AV32(12.8,11.7) AV33(12.8,12.5) AW1(13.6,-12.9) AW2(13.6,-12.1) AW3(13.6,-11.3) AW4(13.6,-10.5) AW30(13.6,10.5) AW31(13.6,11.3) AW32(13.6,12.1) AW33(13.6,12.9) AY1(14.4,-12.5) AY2(14.4,-11.7) AY4(14.5,-10.4) AY5(14.5,-9.6) AY6(14.5,-8.8) AY7(14.5,-8) AY8(14.5,-7.2) AY9(14.5,-6.4) AY10(14.5,-5.6) AY11(14.5,-4.8) AY12(14.5,-4) AY13(14.5,-3.2) AY14(14.5,-2.4) AY15(14.5,-1.6) AY16(14.5,-0.8) AY17(14.5,0) AY18(14.5,0.8) AY19(14.5,1.6) AY20(14.5,2.4) AY21(14.5,3.2) AY22(14.5,4) AY23(14.5,4.8) AY24(14.5,5.6) AY25(14.5,6.4) AY26(14.5,7.2) AY27(14.5,8) AY28(14.5,8.8) AY29(14.5,9.6) AY30(14.5,10.4) AY32(14.4,11.7) AY33(14.4,12.5) B4(-15.7,-10.4) B5(-16.1,-9.6) B6(-15.7,-8.8) B7(-16.1,-8) B8(-15.7,-7.2) B9(-16.1,-6.4) B10(-15.7,-5.6) B11(-16.1,-4.8) B12(-15.7,-4) B13(-16.1,-3.2) B14(-15.7,-2.4) B15(-16.1,-1.6) B16(-15.7,-0.8) B17(-16.1,0) B18(-15.7,0.8) B19(-16.1,1.6) B20(-15.7,2.4) B21(-16.1,3.2) B22(-15.7,4) B23(-16.1,4.8) B24(-15.7,5.6) B25(-16.1,6.4) B26(-15.7,7.2) B27(-16.1,8) B28(-15.7,8.8) B29(-16.1,9.6) B30(-15.7,10.4) BA3(15.3,-11.2) BA5(15.3,-9.6) BA7(15.3,-8) BA9(15.3,-6.4) BA11(15.3,-4.8) BA13(15.3,-3.2) BA15(15.3,-1.6) BA17(15.3,0) BA19(15.3,1.6) BA21(15.3,3.2) BA23(15.3,4.8) BA25(15.3,6.4) BA27(15.3,8) BA29(15.3,9.6) BA31(15.3,11.2) BB4(15.7,-10.4) BB5(16.1,-9.6) BB6(15.7,-8.8) BB7(16.1,-8) BB8(15.7,-7.2) BB9(16.1,-6.4) BB10(15.7,-5.6) BB11(16.1,-4.8) BB12(15.7,-4) BB13(16.1,-3.2) BB14(15.7,-2.4) BB15(16.1,-1.6) BB16(15.7,-0.8) BB17(16.1,0) BB18(15.7,0.8) BB19(16.1,1.6) BB20(15.7,2.4) BB21(16.1,3.2) BB22(15.7,4) BB23(16.1,4.8) BB24(15.7,5.6) BB25(16.1,6.4) BB26(15.7,7.2) BB27(16.1,8) BB28(15.7,8.8) BB29(16.1,9.6) BB30(15.7,10.4) BC4(16.5,-10.4) BC5(16.9,-9.6) BC6(16.5,-8.8) BC7(16.9,-8) BC8(16.5,-7.2) BC9(16.9,-6.4) BC10(16.5,-5.6) BC11(16.9,-4.8) BC12(16.5,-4) BC13(16.9,-3.2) BC14(16.5,-2.4) BC15(16.9,-1.6) BC16(16.5,-0.8) BC17(16.9,0) BC18(16.5,0.8) BC19(16.9,1.6) BC20(16.5,2.4) BC21(16.9,3.2) BC22(16.5,4) BC23(16.9,4.8) BC24(16.5,5.6) BC25(16.9,6.4) BC26(16.5,7.2) BC27(16.9,8) BC28(16.5,8.8) BC29(16.9,9.6) BC30(16.5,10.4) C3(-15.3,-11.2) C5(-15.3,-9.6) C7(-15.3,-8) C9(-15.3,-6.4) C11(-15.3,-4.8) C13(-15.3,-3.2) C15(-15.3,-1.6) C17(-15.3,0) C19(-15.3,1.6) C21(-15.3,3.2) C23(-15.3,4.8) C25(-15.3,6.4) C27(-15.3,8) C29(-15.3,9.6) C31(-15.3,11.2) D1(-14.4,-12.5) D2(-14.4,-11.7) D4(-14.5,-10.4) D5(-14.5,-9.6) D6(-14.5,-8.8) D7(-14.5,-8) D8(-14.5,-7.2) D9(-14.5,-6.4) D10(-14.5,-5.6) D11(-14.5,-4.8) D12(-14.5,-4) D13(-14.5,-3.2) D14(-14.5,-2.4) D15(-14.5,-1.6) D16(-14.5,-0.8) D17(-14.5,0) D18(-14.5,0.8) D19(-14.5,1.6) D20(-14.5,2.4) D21(-14.5,3.2) D22(-14.5,4) D23(-14.5,4.8) D24(-14.5,5.6) D25(-14.5,6.4) D26(-14.5,7.2) D27(-14.5,8) D28(-14.5,8.8) D29(-14.5,9.6) D30(-14.5,10.4) D32(-14.4,11.7) D33(-14.4,12.5) E1(-13.6,-12.9) E2(-13.6,-12.1) E3(-13.6,-11.3) E4(-13.6,-10.5) E30(-13.6,10.5) E31(-13.6,11.3) E32(-13.6,12.1) E33(-13.6,12.9) F1(-12.8,-12.5) F2(-12.8,-11.7) F4(-12.8,-10.5) F30(-12.8,10.5) F32(-12.8,11.7) F33(-12.8,12.5) G1(-12,-12.9) G2(-12,-12.1) G3(-12,-11.3) G4(-12,-10.5) G30(-12,10.5) G31(-12,11.3) G32(-12,12.1) G33(-12,12.9) H1(-11.2,-12.5) H2(-11.2,-11.7) H4(-11.2,-10.5) H30(-11.2,10.5) H32(-11.2,11.7) H33(-11.2,12.5) J1(-10.4,-12.9) J2(-10.4,-12.1) J3(-10.4,-11.3) J4(-10.4,-10.5) J30(-10.4,10.5) J31(-10.4,11.3) J32(-10.4,12.1) J33(-10.4,12.9) K1(-9.6,-12.5) K2(-9.6,-11.7) K4(-9.6,-10.5) K30(-9.6,10.5) K32(-9.6,11.7) K33(-9.6,12.5) L1(-8.8,-12.9) L2(-8.8,-12.1) L3(-8.8,-11.3) L4(-8.8,-10.5) L30(-8.8,10.5) L31(-8.8,11.3) L32(-8.8,12.1) L33(-8.8,12.9) M1(-8,-12.5) M2(-8,-11.7) M4(-8,-10.5) M30(-8,10.5) M32(-8,11.7) M33(-8,12.5) N1(-7.2,-12.9) N2(-7.2,-12.1) N3(-7.2,-11.3) N4(-7.2,-10.5) N30(-7.2,10.5) N31(-7.2,11.3) N32(-7.2,12.1) N33(-7.2,12.9) P1(-6.4,-12.5) P2(-6.4,-11.7) P4(-6.4,-10.5) P30(-6.4,10.5) P32(-6.4,11.7) P33(-6.4,12.5) R1(-5.6,-12.9) R2(-5.6,-12.1) R3(-5.6,-11.3) R4(-5.6,-10.5) R30(-5.6,10.5) R31(-5.6,11.3) R32(-5.6,12.1) R33(-5.6,12.9) T1(-4.8,-12.5) T2(-4.8,-11.7) T4(-4.8,-10.5) T30(-4.8,10.5) T32(-4.8,11.7) T33(-4.8,12.5) U1(-4,-12.9) U2(-4,-12.1) U3(-4,-11.3) U4(-4,-10.5) U30(-4,10.5) U31(-4,11.3) U32(-4,12.1) U33(-4,12.9) V1(-3.2,-12.5) V2(-3.2,-11.7) V4(-3.2,-10.5) V30(-3.2,10.5) V32(-3.2,11.7) V33(-3.2,12.5) W1(-2.4,-12.9) W2(-2.4,-12.1) W3(-2.4,-11.3) W4(-2.4,-10.5) W30(-2.4,10.5) W31(-2.4,11.3) W32(-2.4,12.1) W33(-2.4,12.9) Y1(-1.6,-12.5) Y2(-1.6,-11.7) Y4(-1.6,-10.5) Y30(-1.6,10.5) Y32(-1.6,11.7) Y33(-1.6,12.5)
